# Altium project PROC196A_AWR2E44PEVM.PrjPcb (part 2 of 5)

## Sheet PROC196A_PMIC_Reference.SchDoc
size 431 x 279 mm; Date: Not shown in title block; ApprovedBy: Not shown in title block; CheckedBy: Not shown in title block; Author: Not shown in title block; CompanyName: Not shown in title block; Engineer: Not shown in title block; Organization: Not shown in title block; Address1: Not shown in title block; Address2: Not shown in title block; Address3: Not shown in title block; Address4: Not shown in title block; DocumentNumber: 6; Revision: Use project parameter SCH_Rev; SheetNumber: 6; SheetTotal: 25; PageSetup: Record=PageOptions¦CenterHorizontal=True¦CenterVertical=True¦PrintScale=1.00¦XCorrection=1.00¦YCorrection=1.00¦PrintKind=0¦BorderSize=5000000¦LeftOffset=0¦BottomOffset=0¦Orientation=2¦PaperLength=1000¦PaperWidth=1000¦Scale=100¦PaperSource=15¦PrintQuality=600¦MediaType=1¦DitherType=10¦PaperKind=Letter¦PrintScaleMode=1
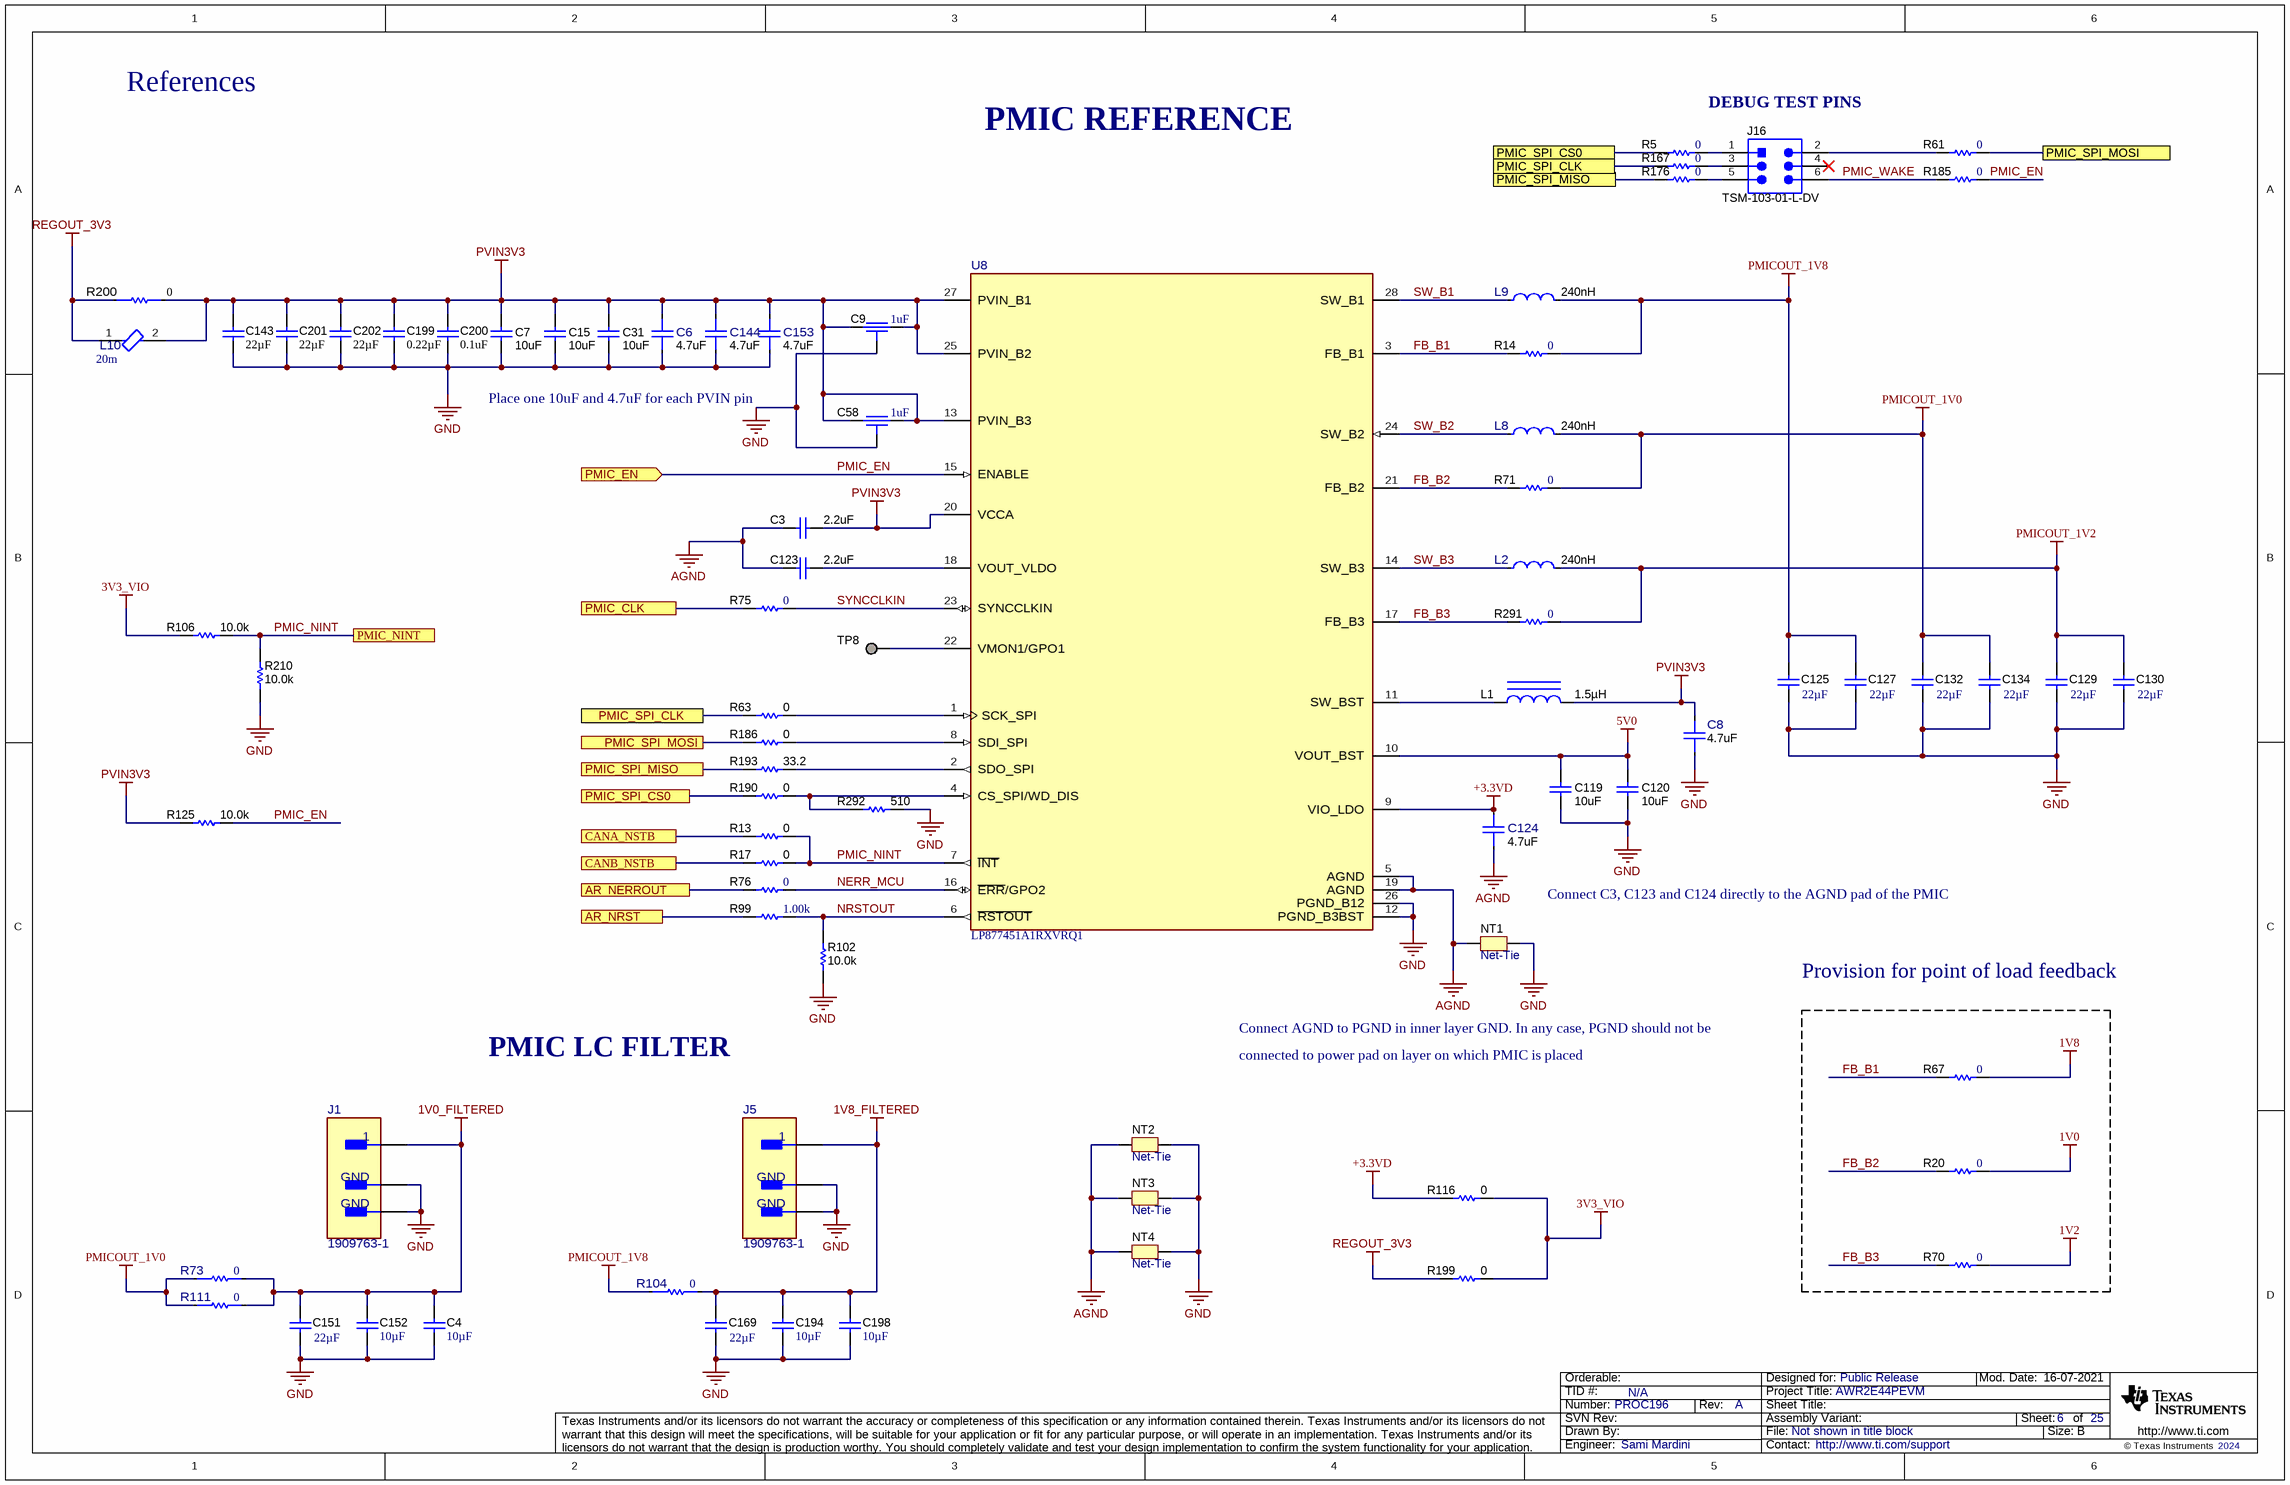
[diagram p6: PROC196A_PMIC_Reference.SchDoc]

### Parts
C3  ValueDisplayed: 2.2uF  [0603L]  (hidden comment: GCM188R70J225KE22D)
C4  Cap_F: 10µF  [0805L]  (hidden comment: C0805C106J8RACAUTO)
C6  ValueDisplayed: 4.7uF  [FP-GCJ188C70J475KE02J_0603-MFG]  (hidden comment: GCJ188C70J475KE02J)
C7  ValueDisplayed: 10uF  [0805L]  (hidden comment: GCM21BR71A106KE22L)
C8  ValueDisplayed: 4.7uF  [FP-GCJ188C70J475KE02J_0603-MFG]  (hidden comment: GCJ188C70J475KE02J)
C9  ValueDisplayed: 1uF  [FP-NFM18HC105C1C3D_0603-MFG]  (hidden comment: NFM18HC105C1C3D)
C15  ValueDisplayed: 10uF  [0805L]  (hidden comment: GCM21BR71A106KE22L)
C31  ValueDisplayed: 10uF  [0805L]  (hidden comment: GCM21BR71A106KE22L)
C58  ValueDisplayed: 1uF  [FP-NFM18HC105C1C3D_0603-MFG]  (hidden comment: NFM18HC105C1C3D)
C119  ValueDisplayed: 10uF  [0805L]  (hidden comment: GCM21BR71A106KE22L)
C120  ValueDisplayed: 10uF  [0805L]  (hidden comment: GCM21BR71A106KE22L)
C123  ValueDisplayed: 2.2uF  [0603L]  (hidden comment: GCM188R70J225KE22D)
C124  ValueDisplayed: 4.7uF  [FP-GCJ188C70J475KE02J_0603-MFG]  (hidden comment: GCJ188C70J475KE02J)
C125  ValueDisplayed: 22µF  [0805_155]  (hidden comment: CGA4J1X7T0J226M)
C127  ValueDisplayed: 22µF  [0805_155]  (hidden comment: CGA4J1X7T0J226M)
C129  ValueDisplayed: 22µF  [0805_155]  (hidden comment: CGA4J1X7T0J226M)
C130  ValueDisplayed: 22µF  [0805_155]  (hidden comment: CGA4J1X7T0J226M)
C132  ValueDisplayed: 22µF  [0805_155]  (hidden comment: CGA4J1X7T0J226M)
C134  ValueDisplayed: 22µF  [0805_155]  (hidden comment: CGA4J1X7T0J226M)
C143  ValueDisplayed: 22µF  [0805_155]  (hidden comment: CGA4J1X7T0J226M)
C144  ValueDisplayed: 4.7uF  [FP-GCJ188C70J475KE02J_0603-MFG]  (hidden comment: GCJ188C70J475KE02J)
C151  ValueDisplayed: 22µF  [0805_155]  (hidden comment: CGA4J1X7T0J226M)
C152  Cap_F: 10µF  [0805L]  (hidden comment: C0805C106J8RACAUTO)
C153  ValueDisplayed: 4.7uF  [FP-GCJ188C70J475KE02J_0603-MFG]  (hidden comment: GCJ188C70J475KE02J)
C169  ValueDisplayed: 22µF  [0805_155]  (hidden comment: CGA4J1X7T0J226M)
C194  Cap_F: 10µF  [0805L]  (hidden comment: C0805C106J8RACAUTO)
C198  Cap_F: 10µF  [0805L]  (hidden comment: C0805C106J8RACAUTO)
C199  ValueDisplayed: 0.22µF  [0402L]  (hidden comment: GCM155R71C224KE02D)
C200  ValueDisplayed: 0.1uF  [0402L]  (hidden comment: GCM155R71C104KA55D)
C201  ValueDisplayed: 22µF  [0805_155]  (hidden comment: CGA4J1X7T0J226M)
C202  ValueDisplayed: 22µF  [0805_155]  (hidden comment: CGA4J1X7T0J226M)
J1  1909763-1  [FP-1909763-1_SMT_JACK _CONN-MFG]
J5  1909763-1  [FP-1909763-1_SMT_JACK _CONN-MFG]
J16  TSM-103-01-L-DV  [Samtec_TSM-103-01-x-DV]
L1  ValueDisplayed: 1.5µH  [TFM201610ALMA]  (hidden comment: TFM201610ALMA1R5MTAA)
L2  Ind_H: 240nH  [FP-TFM201610ALMAR24MTAA_0806 (2016 Metric)-MFG]  (hidden comment: TFM201610ALMAR24MTAA)
L8  Ind_H: 240nH  [FP-TFM201610ALMAR24MTAA_0806 (2016 Metric)-MFG]  (hidden comment: TFM201610ALMAR24MTAA)
L9  Ind_H: 240nH  [FP-TFM201610ALMAR24MTAA_0806 (2016 Metric)-MFG]  (hidden comment: TFM201610ALMAR24MTAA)
L10  DCR_ohm: 20m  [FP-MPZ2012S101ATD25_0805-MFG]  (hidden comment: MPZ2012S101ATD25)
NT1  Net-Tie  [Net-Tie_50milWide_30milLong]  (net tie, no BOM)
NT2  Net-Tie  [Net-Tie_50milWide_30milLong]  (net tie, no BOM)
NT3  Net-Tie  [Net-Tie_50milWide_30milLong]  (net tie, no BOM)
NT4  Net-Tie  [Net-Tie_50milWide_30milLong]  (net tie, no BOM)
R5  ValueDisplayed: 0  [0402L]  (hidden comment: ERJ-2GE0R00X)
R13  ValueDisplayed: 0  [0402L]  (hidden comment: ERJ-2GE0R00X)
R14  ValueDisplayed: 0  [0402L]  (hidden comment: ERJ-2GE0R00X)
R17  ValueDisplayed: 0  [0402L]  (hidden comment: ERJ-2GE0R00X)
R20  ValueDisplayed: 0  [0402L]  (hidden comment: ERJ-2GE0R00X)
R61  ValueDisplayed: 0  [0402L]  (hidden comment: ERJ-2GE0R00X)
R63  ValueDisplayed: 0  [0402L]  (hidden comment: ERJ-2GE0R00X)
R67  ValueDisplayed: 0  [0402L]  (hidden comment: ERJ-2GE0R00X)
R70  ValueDisplayed: 0  [0402L]  (hidden comment: ERJ-2GE0R00X)
R71  ValueDisplayed: 0  [0402L]  (hidden comment: ERJ-2GE0R00X)
R73  value 0  [FP-HCJ0603ZT0R00_0603-MFG]  (hidden comment: HCJ0603ZT0R00)
R75  ValueDisplayed: 0  [0402L]  (hidden comment: ERJ-2GE0R00X)
R76  ValueDisplayed: 0  [0402L]  (hidden comment: ERJ-2GE0R00X)
R99  ValueDisplayed: 1.00k  [0402L]  (hidden comment: CRCW04021K00FKED)
R102  ValueDisplayed: 10.0k  [0402L]  (hidden comment: CRCW040210K0FKED)
R104  value 0  [FP-HCJ0603ZT0R00_0603-MFG]  (hidden comment: HCJ0603ZT0R00)
R106  ValueDisplayed: 10.0k  [0402L]  (hidden comment: CRCW040210K0FKED)
R111  value 0  [FP-HCJ0603ZT0R00_0603-MFG]  (hidden comment: HCJ0603ZT0R00)
R116  ValueDisplayed: 0  [0402L]  (hidden comment: CRCW04020000Z0EDHP)
R125  ValueDisplayed: 10.0k  [0402L]  (hidden comment: CRCW040210K0FKED)
R167  ValueDisplayed: 0  [0402L]  (hidden comment: ERJ-2GE0R00X)
R176  ValueDisplayed: 0  [0402L]  (hidden comment: ERJ-2GE0R00X)
R185  ValueDisplayed: 0  [0402L]  (hidden comment: ERJ-2GE0R00X)
R186  ValueDisplayed: 0  [0402L]  (hidden comment: ERJ-2GE0R00X)
R190  ValueDisplayed: 0  [0402L]  (hidden comment: ERJ-2GE0R00X)
R193  ValueDisplayed: 33.2  [0402L]  (hidden comment: CRCW040233R2FKED)
R199  ValueDisplayed: 0  [0402L]  (hidden comment: CRCW04020000Z0EDHP)
R200  Res_ohm: 0  [FP-HCJ0603ZT0R00_0603-MFG]  (hidden comment: HCJ0603ZT0R00)
R210  ValueDisplayed: 10.0k  [0402L]  (hidden comment: CRCW040210K0FKED)
R291  ValueDisplayed: 0  [0402L]  (hidden comment: ERJ-2GE0R00X)
R292  ValueDisplayed: 510  [0402L]  (hidden comment: ERJ-2GEJ511X)
TP8  TESTPOINT  [TP_25MIL-SMT]  (value not drawn)  (no BOM)
U8  LP877451A1RXVRQ1  [RXV0028A-MFG]

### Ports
AR_NERROUT, AR_NRST, CANA_NSTB, CANB_NSTB, PMIC_CLK, PMIC_EN (in), PMIC_NINT, PMIC_SPI_CLK, PMIC_SPI_CS0, PMIC_SPI_MISO, PMIC_SPI_MOSI

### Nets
1V0: R20.2
1V0_FILTERED: C4.1 C151.1 C152.1 J1.1 R73.2 R111.2
1V2: R70.2
1V8: R67.2
1V8_FILTERED: C169.1 C194.1 C198.1 J5.1 R104.2
3V3_VIO: R106.2 R116.2 R199.2
5V0: C119.1 C120.1 U8.10(VOUT_BST)
+3.3VD: C124.2 R116.1 U8.9(VIO_LDO)
AGND: C3.1 C123.1 C124.1 NT1.2 NT2.1 NT3.1 NT4.1 U8.5(AGND) U8.19(AGND)
GND: C4.2 C6.1 C7.2 C8.1 C9.2 C15.2 C31.2 C58.2 C119.2 C120.2 C125.2 C127.2 C129.2 C130.2 C132.2 C134.2 C143.2 C144.1 C151.2 C152.2 C153.1 C169.2 C194.2 C198.2 C199.2 C200.2 C201.2 C202.2 J1.2(GND) J1.3(GND) J5.2(GND) J5.3(GND) NT1.1 NT2.2 NT3.2 NT4.2 R102.2 R210.2 R292.1 U8.12(PGND_B3BST) U8.26(PGND_B12)
PMICOUT_1V0: C132.1 C134.1 L8.2 R71.2 R73.1 R111.1
PMICOUT_1V2: C129.1 C130.1 L2.2 R291.2
PMICOUT_1V8: C125.1 C127.1 L9.2 R14.2 R104.1
PVIN3V3: C3.2 C6.2 C7.1 C8.2 C9.1 C9.3 C15.1 C31.1 C58.1 C58.3 C143.1 C144.2 C153.2 C199.1 C200.1 C201.1 C202.1 L1.2 L10.2 R125.2 R200.2 U8.13(PVIN_B3) U8.20(VCCA) U8.25(PVIN_B2) U8.27(PVIN_B1)
REGOUT_3V3: L10.1 R199.1 R200.1
AR_NERROUT: R76.1 ; port AR_NERROUT
AR_NRST: R99.1 ; port AR_NRST
CANA_NSTB: R13.1 ; port CANA_NSTB
CANB_NSTB: R17.1 ; port CANB_NSTB
FB_B1: R14.1 R67.1 U8.3(FB_B1)
FB_B2: R20.1 R71.1 U8.21(FB_B2)
FB_B3: R70.1 R291.1 U8.17(FB_B3)
NERR_MCU: R76.2 U8.16(~{ERR}/GPO2)
NRSTOUT: R99.2 R102.1 U8.6(~{RSTOUT})
PMIC_CLK: R75.1 ; port PMIC_CLK
PMIC_EN: R125.1 R185.2 U8.15(ENABLE) ; port PMIC_EN
PMIC_NINT: R13.2 R17.2 R106.1 R210.1 U8.7(~{INT}) ; port PMIC_NINT
PMIC_SPI_CLK: R63.2 R167.1 ; port PMIC_SPI_CLK
PMIC_SPI_CS0: R5.1 R190.1 ; port PMIC_SPI_CS0
PMIC_SPI_MISO: R176.1 R193.2 ; port PMIC_SPI_MISO
PMIC_SPI_MOSI: R61.2 R186.2 ; port PMIC_SPI_MOSI
PMIC_WAKE: J16.6 R185.1
SW_B1: L9.1 U8.28(SW_B1)
SW_B2: L8.1 U8.24(SW_B2)
SW_B3: L2.1 U8.14(SW_B3)
SYNCCLKIN: R75.2 U8.23(SYNCCLKIN)
NetC123_2: C123.2 U8.18(VOUT_VLDO)
NetJ16_1: J16.1 R5.2
NetJ16_2: J16.2 R61.1
NetJ16_3: J16.3 R167.2
NetJ16_5: J16.5 R176.2
NetL1_1: L1.1 U8.11(SW_BST)
NetR63_1: R63.1 U8.1(SCK_SPI)
NetR186_1: R186.1 U8.8(SDI_SPI)
NetR190_2: R190.2 R292.2 U8.4(CS_SPI/WD_DIS)
NetR193_1: R193.1 U8.2(SDO_SPI)
NetTP8_1: TP8.1 U8.22(VMON1/GPO1)

Not connected (* = marked no-connect by the designer): J16 4*

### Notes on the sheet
- References
- PMIC REFERENCE
- DEBUG TEST PINS
- Place one 10uF and 4.7uF for each PVIN pin
- Connect C3, C123 and C124 directly to the AGND pad of the PMIC
- Connect AGND to PGND in inner layer GND. In any case, PGND should not be
- Provision for point of load feedback
- PMIC LC FILTER
- connected to power pad on layer on which PMIC is placed

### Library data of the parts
C3 C123 = CMP-0007134-5: CAP, CERM, 2.2 uF, 6.3 V, +/- 10%, X7R, AEC-Q200 Grade 1, 0603; Manufacturer: MuRata; TaMin_C: -55°C; Polarized: N; SizeAreaWB_mm2: 4.68; Value1: Unknown; U/M: EA; Value: 2.2uF; TaMax_C: 125°C; SizeZ_mm: 1; SizeX_mm: 1.6; SizeY_mm: 0.8; Cap_Case: 0603; Value2: 6.3V; SizeArea_mm2: 1.28; AEC Qualified: Y; Cap_F: 2.2µF; AEC Category: Q200
C4 C152 C194 C198 = CMP-0081061-1: CAP, CERM, 10 µF, 10 V,+/- 5%, X7R, AEC-Q200 Grade 1, 0805; Manufacturer: Kemet; TaMin_C: -55°C; Polarized: N; SizeAreaWB_mm2: 6.75; U/M: EA; Value: 10uF; TaMax_C: 125°C; SizeZ_mm: 1.45; SizeX_mm: 2; SizeY_mm: 1.25; Cap_Case: 0805; Value2: 10V; SizeArea_mm2: 2.5; AEC Qualified: Y; AEC Grade: 1; AEC Category: Q200
C6 C8 C124 C144 C153 = CMP-0091520-1: Cap Ceramic Multilayer 4.7uF 6.3V DC 10% SMD Paper T/R; Manufacturer: Murata; AEC Grade: Grade 1; TempCo: 22%; SizeZ_mm: 1mm; Temperature Characteristic: X7S; Cap_F: 4.7µF; Value: 4.7µF; AEC Qualified: Yes
C7 C15 C31 C119 C120 = CMP-0008017-2: CAP, CERM, 10 uF, 10 V, +/- 10%, X7R, 0805; Manufacturer: MuRata; TaMin_C: -55°C; Polarized: N; SizeAreaWB_mm2: 6.75; Value1: Unknown; U/M: EA; Value: 10uF; TaMax_C: 125°C; SizeZ_mm: 1.45; SizeX_mm: 2; SizeY_mm: 1.25; Cap_Case: 0805; Value2: 10V; SizeArea_mm2: 2.5; Cap_F: 10µF; AEC Category: Q200
C9 C58 = CMP-0088247-2: 3 Terminals Low ESL Chip Multilayer Ceramic Capacitors for Automotive; Manufacturer: Murata; VDC_V: 16V; SizeZ_mm: 0.7mm; Tolerance_%: 20%; AEC Grade: Grade 1; Cap_F: 1µF; AEC Qualified: Yes
C125 C127 C129 C130 C132 C134 = CMP-0860846-1: CAP, CERM, 22 µF, 6.3 V,+/- 20%, X7T, AEC-Q200 Grade 1, 0805; Manufacturer: TDK; Alternate PartNumber: CGA4J1X7T0J226M125AC; TaMin_C: -55°C; Polarized: N; SizeAreaWB_mm2: 6.75; U/M: EA; Value: 22uF; TaMax_C: 125°C; SizeZ_mm: 1.55; SizeX_mm: 2; SizeY_mm: 1.25; Cap_Case: 0805; Value2: 6.3V; SizeArea_mm2: 2.5; AEC Qualified: Y; AEC Grade: 1; AEC Category: Q200
C143 C201 C202 = CMP-0860846-1: CAP, CERM, 22 µF, 6.3 V,+/- 20%, X7T, AEC-Q200 Grade 1, 0805; Manufacturer: TDK; AEC Grade: 1; Value2: 6.3V; U/M: EA; Value: 22uF; TaMin_C: -55°C; TaMax_C: 125°C; SizeArea_mm2: 2.5; SizeAreaWB_mm2: 6.75; SizeX_mm: 2; Polarized: N; Cap_Case: 0805; AEC Qualified: Y; AEC Category: Q200; SizeZ_mm: 1.55; SizeY_mm: 1.25
C151 C169 = CMP-0860846-1: CAP, CERM, 22 µF, 6.3 V,+/- 20%, X7T, AEC-Q200 Grade 1, 0805; Manufacturer: TDK; TaMin_C: -55°C; Polarized: N; SizeAreaWB_mm2: 6.75; U/M: EA; Value: 22uF; TaMax_C: 125°C; SizeZ_mm: 1.55; SizeX_mm: 2; SizeY_mm: 1.25; Cap_Case: 0805; Value2: 6.3V; SizeArea_mm2: 2.5; AEC Qualified: Y; AEC Grade: 1; AEC Category: Q200
C199 = CMP-0078265-1: CAP, CERM, 0.22 µF, 16 V,+/- 10%, X7R, AEC-Q200 Grade 1, 0402; Manufacturer: MuRata; TaMin_C: -55°C; Polarized: N; SizeAreaWB_mm2: 3; U/M: EA; Value: 0.22uF; TaMax_C: 125°C; SizeZ_mm: 0.6; SizeX_mm: 1; SizeY_mm: 0.5; Cap_Case: 0402; Value2: 16V; AEC Qualified: Y; Cap_F: 220nF; AEC Category: Q200
C200 = CMP-0006351-2: CAP, CERM, 0.1 uF, 16 V, +/- 10%, X7R, 0402; Manufacturer: MuRata; TaMin_C: -55°C; Polarized: N; SizeAreaWB_mm2: 3; Value1: Unknown; U/M: EA; Value: 0.1uF; TaMax_C: 125°C; SizeZ_mm: 0.6; SizeX_mm: 1; SizeY_mm: 0.5; Cap_Case: 0402; Value2: 16V; Cap_F: 100nF; AEC Category: Q200
J1 J5 = CMP-0091846-1: U.FL (UMCC) Connector Jack, Male Pin 50Ohm Surface Mount Solder; Manufacturer: TE Connectivity; Conn Orientation: Vertical; AEC Qualified: No; SizeZ_mm: 1.5mm; Impedance: 50Ω; Frequency_Fixed: 0-6GHz; ContactFinish: Gold,Nickel; Dielectric Material: Liquid Crystal Polymer
J16 = CMP-0075648-2: Header, 2.54mm, 3x2, Gold, SMT; Manufacturer: Samtec; Pitch_mm: 2.54; Gender: Male; Cert_CSA: Y; Green_REACh: Passed; Current_A: 4.9A; Voltage_V: 475V; Shrouded: N; Green_Lifecycle: Active; Row_Count: 2
L1 = CMP-0081093-1: Inductor, Shielded, Metal Composite, 1.5 µH, 2.3 A, 0.11 ohm, AEC-Q200 Grade 0, SMD; Manufacturer: TDK; Isat: 2.8A @ 30% inductance drop; Irms: 2.3A @ 40C rise; SizeAreaWB_mm2: 7.8; DCR_ohm: 0.11; Value: 1.5uH; Imax_A: 2.3A; SizeZ_mm: 1; SizeX_mm: 2; SizeY_mm: 1.6; SizeArea_mm2: 3.2; AEC Qualified: Y; AEC Grade: 0; AEC Category: Q200
L2 L8 L9 = CMP-0091696-1: 240nH Shielded Thin Film Inductor 5A 23mOhm Max 0806 (2016 Metric); Manufacturer: TDK; SizeZ_mm: 1mm; Material: Metal; Irms: 6.5A; Shrouded: true; Value: 0.24uH; AEC Qualified: Yes; DCR_ohm: 0.023; AEC Grade: Grade 0; Test Frequency: 1MHz; Tolerance_%: 20%
L10 = CMP-0089947-1: 100 Ohms @ 100MHz 1 Power Line Ferrite Bead 0805 (2012 Metric) 4A 20mOhm; Manufacturer: TDK; AEC Grade: Grade 1; Impedance At Frequency: 100Ω @ 100MHz; SizeZ_mm: 1.05mm; AEC Qualified: Yes; Tolerance_%: 25%
NT1 = CMP-0078142-4: Single point connection between nets.
NT2-NT4 = CMP-0078142-3: Single point connection between nets.
R5 R14 R20 R61 R67 R70 R71 R75 R76 R167 R176 R185 R291 = CMP-0026992-3: RES, 0, 5%, 0.1 W, AEC-Q200 Grade 0, 0402; Manufacturer: Panasonic; Power_W: 100mW; TempCo: 600 ppm/C; Value_Code: 0000; Value: 0; EIA_Code: E24; SizeX_mm: 1; SizeY_mm: 0.5; SizeZ_mm: 0.6; Value2: 0.1W; CompType: Resistor; AEC Qualified: Y; VDC_V: 50V; AEC Category: Q200; SizeAreaWB_mm2: 3; INSTALLATION: DNP
R13 R17 R63 R186 R190 = CMP-0026992-3: RES, 0, 5%, 0.1 W, AEC-Q200 Grade 0, 0402; Manufacturer: Panasonic; Power_W: 100mW; TempCo: 600 ppm/C; Value_Code: 0000; Value: 0; EIA_Code: E24; SizeX_mm: 1; SizeY_mm: 0.5; SizeZ_mm: 0.6; Value2: 0.1W; AEC Qualified: Y; VDC_V: 50V; AEC Category: Q200; SizeAreaWB_mm2: 3
R73 R104 R111 = CMP-0091690-1: RES 0 OHM JUMPER 1/4W 0603; Manufacturer: Stackpole Electronics; Power_W: 250mW; AEC Grade: Grade 0; AEC Qualified: Yes; SizeZ_mm: 0.7mm
R99 = CMP-0026071-3: RES, 1.00 k, 1%, 0.063 W, AEC-Q200 Grade 0, 0402; Manufacturer: Vishay-Dale; Power_W: 63mW; TempCo: 100 ppm/C; Value_Code: 1k00; Value: 1.00k; EIA_Code: E96; Res_ohm: 1k; SizeX_mm: 1; SizeY_mm: 0.5; SizeZ_mm: 0.6; Value2: 0.063W; AEC Qualified: Y; VDC_V: 50V; AEC Category: Q200; AEC Grade: 0
R102 R106 R125 R210 = CMP-0025958-3: RES, 10.0 k, 1%, 0.063 W, AEC-Q200 Grade 0, 0402; Manufacturer: Vishay-Dale; Power_W: 63mW; TempCo: 100 ppm/C; Value_Code: 10k0; Value: 10.0k; EIA_Code: E96; Res_ohm: 10k; SizeX_mm: 1; SizeY_mm: 0.5; SizeZ_mm: 0.6; Value2: 0.063W; AEC Qualified: Y; VDC_V: 50V; AEC Category: Q200; AEC Grade: 0
R116 R199 = CMP-0081856-1: RES, 0, 0%, 0.2 W, AEC-Q200 Grade 0, 0402; Manufacturer: Vishay-Dale; SizeAreaWB_mm2: 3; SizeArea_mm2: 0.5; AEC Qualified: Y; AEC Category: Q200; Value: 0; SizeZ_mm: 0.6; Power_W: 200mW; VDC_V: 50V; Value2: 0.2W; SizeX_mm: 1
R193 = CMP-0026299-2: RES, 33.2, 1%, 0.063 W, AEC-Q200 Grade 0, 0402; Manufacturer: Vishay-Dale; Power_W: 63mW; TempCo: 100 ppm/C; Value_Code: 33R2; Value: 33.2; EIA_Code: E96; SizeX_mm: 1; SizeY_mm: 0.5; SizeZ_mm: 0.6; Value2: 0.063W; AEC Qualified: Y; VDC_V: 50V; AEC Category: Q200; AEC Grade: 0
R200 = CMP-0091690-1: RES 0 OHM JUMPER 1/4W 0603; Manufacturer: Stackpole Electronics; Power_W: 250mW; AEC Grade: Grade 0; AEC Qualified: Yes; SizeZ_mm: 0.7mm; Value: 0
R292 = CMP-0078212-1: RES, 510, 5%, 0.1 W, AEC-Q200 Grade 0, 0402; Manufacturer: Panasonic; Value_Code: 510R; SizeArea_mm2: 0.5; AEC Qualified: Y; AEC Category: Q200; Value: 510; SizeZ_mm: 0.6; EIA_Code: E24; TempCo: 200 ppm/C; AEC Grade: 0; Power_W: 100mW; VDC_V: 50V; Value2: 0.1W; U/M: EA; SizeX_mm: 1
TP8 = CMP-0078143-3: TEST POINT.  No entry in BOM.
U8 = CMP-0091078-3: Three Buck Converters and 5-V Boost for AWR and IWR Radar Sensors; Manufacturer: Texas Instruments; CompType: IC; AEC Category: Q200; Standoff Height: 0mm; Min Supply Voltage: 3V; TJmax_C: +150°C; Switching Frequency: 4.4-8.8-17.6MHz; Nominal Supply Current: 3uA; TaMax_C: +125°C; Max Supply Voltage: 4V; TaMin_C: -40°C; Number Of Outputs: 4; SizeZ_mm: 1mm; Output Voltage: 0.9-1.9V; AEC Qualified: Yes; AEC Grade: Grade 1; Output Type: AdjustableProgrammable

## Sheet PROC196A_3V3_Supply_Reference.SchDoc
size 431 x 279 mm; Date: Not shown in title block; ApprovedBy: Not shown in title block; CheckedBy: Not shown in title block; Author: Not shown in title block; CompanyName: Not shown in title block; Engineer: Not shown in title block; Organization: Not shown in title block; Address1: Not shown in title block; Address2: Not shown in title block; Address3: Not shown in title block; Address4: Not shown in title block; DocumentNumber: 7; Revision: Use project parameter SCH_Rev; SheetNumber: 7; SheetTotal: 25; PageSetup: Record=PageOptions¦CenterHorizontal=True¦CenterVertical=True¦PrintScale=1.00¦XCorrection=1.00¦YCorrection=1.00¦PrintKind=0¦BorderSize=5000000¦LeftOffset=0¦BottomOffset=0¦Orientation=2¦PaperLength=1000¦PaperWidth=1000¦Scale=100¦PaperSource=15¦PrintQuality=600¦MediaType=1¦DitherType=10¦PaperKind=Letter¦PrintScaleMode=1
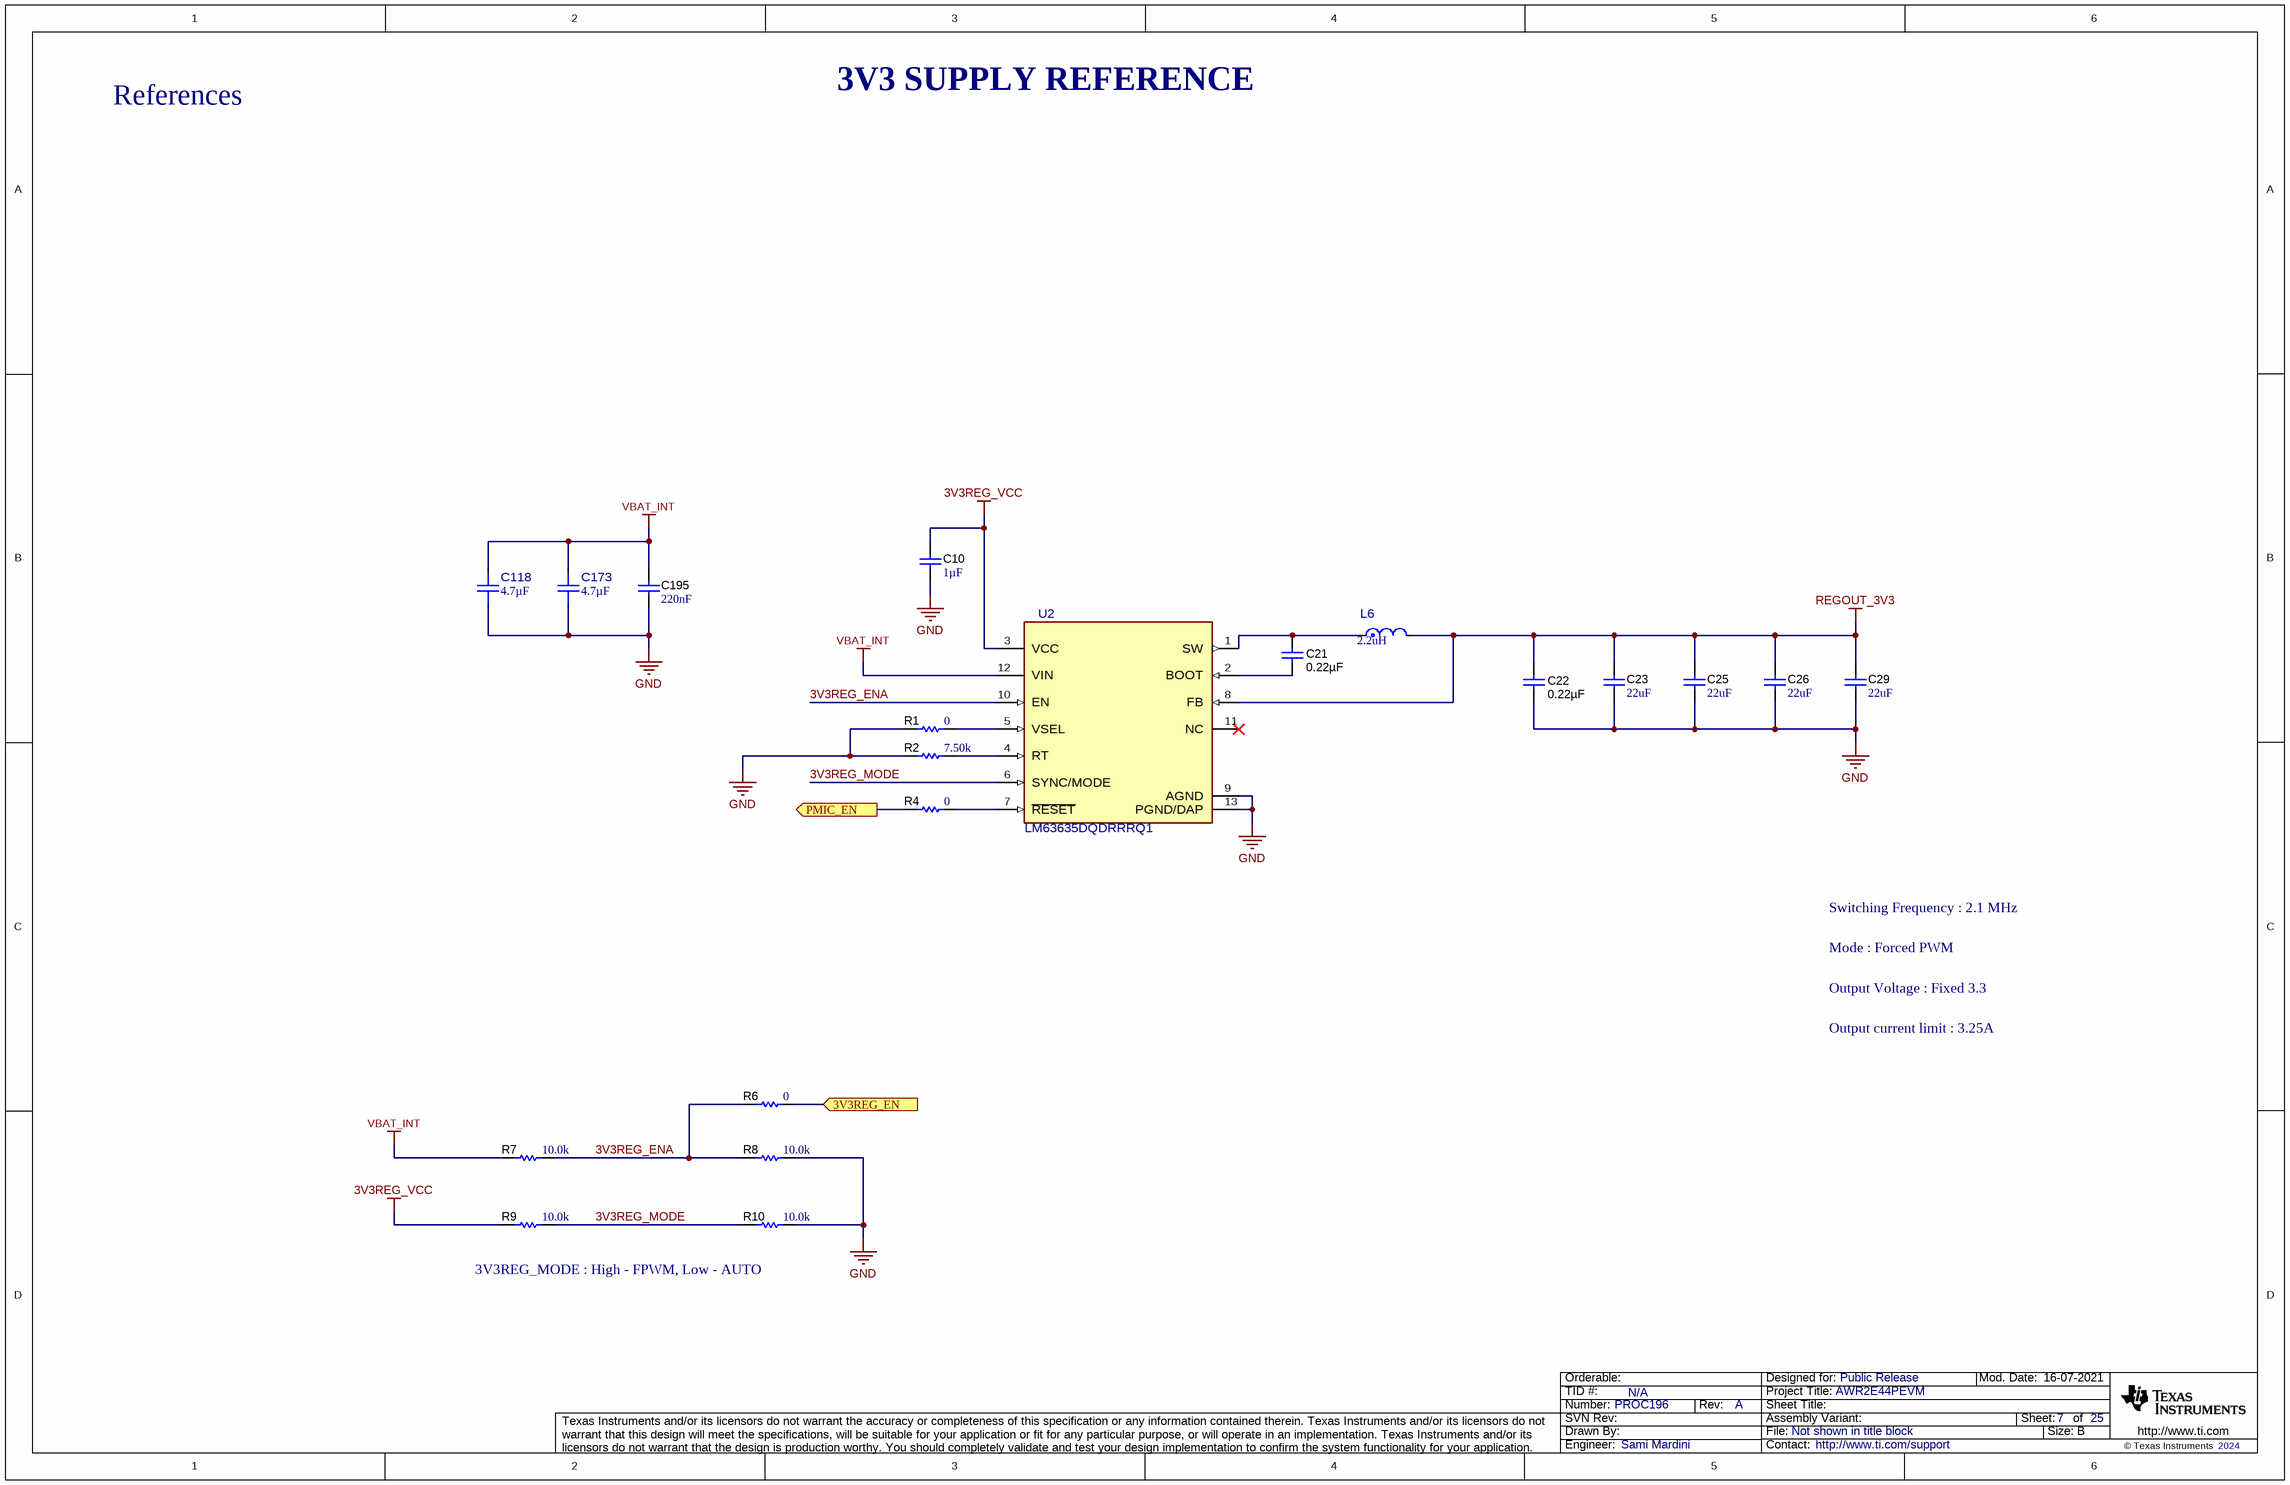
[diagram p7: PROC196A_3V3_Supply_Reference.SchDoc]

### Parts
C10  Cap_F: 1µF  [0603L]  (hidden comment: GCM188R71C105KA64D)
C21  ValueDisplayed: 0.22µF  [0402L]  (hidden comment: GCM155R71C224KE02D)
C22  ValueDisplayed: 0.22µF  [0402L]  (hidden comment: GCM155R71C224KE02D)
C23  ValueDisplayed: 22uF  [1206_180L]  (hidden comment: GCM31CR71A226KE02L)
C25  ValueDisplayed: 22uF  [1206_180L]  (hidden comment: GCM31CR71A226KE02L)
C26  ValueDisplayed: 22uF  [1206_180L]  (hidden comment: GCM31CR71A226KE02L)
C29  ValueDisplayed: 22uF  [1206_180L]  (hidden comment: GCM31CR71A226KE02L)
C118  Cap_F: 4.7µF  [FP-CGA4J1X7R1H475K125AC_0805-MFG]  (hidden comment: CGA4J1X7R1H475K125AC)
C173  Cap_F: 4.7µF  [FP-CGA4J1X7R1H475K125AC_0805-MFG]  (hidden comment: CGA4J1X7R1H475K125AC)
C195  Cap_F: 220nF  [0603L]  (hidden comment: CGA3E3X7R1H224K080AB)
L6  value 2.2uH  [FP-XEL4030-222MEC_SMT2_4MM0_4MM0-MFG]  (hidden comment: XEL4030-222MEC)
R1  ValueDisplayed: 0  [0402L]  (hidden comment: ERJ-2GE0R00X)
R2  ValueDisplayed: 7.50k  [0402L]  (hidden comment: CRCW04027K50FKED)
R4  ValueDisplayed: 0  [0402L]  (hidden comment: ERJ-2GE0R00X)
R6  ValueDisplayed: 0  [0402L]  (hidden comment: ERJ-2GE0R00X)
R7  ValueDisplayed: 10.0k  [0402L]  (hidden comment: CRCW040210K0FKED)
R8  ValueDisplayed: 10.0k  [0402L]  (hidden comment: CRCW040210K0FKED)
R9  ValueDisplayed: 10.0k  [0402L]  (hidden comment: CRCW040210K0FKED)
R10  ValueDisplayed: 10.0k  [0402L]  (hidden comment: CRCW040210K0FKED)
U2  LM63635DQDRRRQ1  [DRR0012E-MFG]

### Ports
3V3REG_EN (in), PMIC_EN (out)

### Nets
3V3REG_VCC: C10.1 R9.2 U2.3(VCC)
GND: C10.2 C22.1 C23.2 C25.2 C26.2 C29.2 C118.1 C173.1 C195.2 R1.2 R2.1 R8.2 R10.1 U2.9(AGND) U2.13(PGND/DAP)
REGOUT_3V3: C22.2 C23.1 C25.1 C26.1 C29.1 L6.2 U2.8(FB)
VBAT_INT: C118.2 C173.2 C195.1 R7.1 U2.12(VIN)
3V3REG_EN: R6.2 ; port 3V3REG_EN
3V3REG_ENA: R6.1 R7.2 R8.1 U2.10(EN)
3V3REG_MODE: R9.1 R10.2 U2.6(SYNC/MODE)
PMIC_EN: R4.1 ; port PMIC_EN
NetC21_1: C21.1 U2.2(BOOT)
NetC21_2: C21.2 L6.1 U2.1(SW)
NetR1_1: R1.1 U2.5(VSEL)
NetR2_2: R2.2 U2.4(RT)
NetR4_2: R4.2 U2.7(~{RESET})

Not connected (* = marked no-connect by the designer): U2 11(NC)*

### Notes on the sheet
- 3V3 SUPPLY REFERENCE
- References
- Switching Frequency : 2.1 MHz
- Mode : Forced PWM
- Output Voltage : Fixed 3.3
- Output current limit : 3.25A
- 3V3REG_MODE : High - FPWM, Low - AUTO

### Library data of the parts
C10 = CMP-0007136-5: CAP, CERM, 1 uF, 16 V, +/- 10%, X7R, AEC-Q200 Grade 1, 0603; Manufacturer: MuRata; TaMin_C: -55°C; Polarized: N; SizeAreaWB_mm2: 4.68; Value1: Unknown; U/M: EA; Value: 1uF; TaMax_C: 125°C; SizeZ_mm: 1; SizeX_mm: 1.6; SizeY_mm: 0.8; Cap_Case: 0603; Value2: 16V; SizeArea_mm2: 1.28; AEC Qualified: Y; AEC Category: Q200
C21 C22 = CMP-0078265-1: CAP, CERM, 0.22 µF, 16 V,+/- 10%, X7R, AEC-Q200 Grade 1, 0402; Manufacturer: MuRata; TaMin_C: -55°C; Polarized: N; SizeAreaWB_mm2: 3; U/M: EA; Value: 0.22uF; TaMax_C: 125°C; SizeZ_mm: 0.6; SizeX_mm: 1; SizeY_mm: 0.5; Cap_Case: 0402; Value2: 16V; CompType: Capacitor; AEC Qualified: Y; Cap_F: 220nF; AEC Category: Q200
C23 C25 C26 C29 = CMP-0008811-3: CAP, CERM, 22 uF, 10 V, +/- 10%, X7R, AEC-Q200 Grade 1, 1206; Manufacturer: MuRata; SizeX_mm: 3.2; SizeArea_mm2: 5.12; Polarized: N; SizeY_mm: 1.6; Value2: 10V; TaMin_C: -55°C; SizeZ_mm: 1.8; Cap_Case: 1206; AEC Grade: 1; Value1: Unknown; U/M: EA; AEC Qualified: Y; SizeAreaWB_mm2: 10.92; AEC Category: Q200; Value: 22uF; Cap_F: 22µF; TaMax_C: 125°C
C118 C173 = CMP-0090082-1: Cap Ceramic 4.7uF 50V X7R 10% Pad SMD 0805 +125°C Automotive T/R; Manufacturer: TDK Corporation; SizeZ_mm: 1.45mm; Tolerance_%: 0.1%; AEC Qualified: Yes; TempCo: 15%; AEC Grade: Grade 1; Value: 4.7µF
C195 = CMP-0007094-5: CAP, CERM, 0.22 uF, 50 V, +/- 10%, X7R, AEC-Q200 Grade 1, 0603; Manufacturer: TDK; TaMin_C: -55°C; ESR_ohm: 0.021699; Polarized: N; SizeAreaWB_mm2: 4.68; Value1: 0.021699 ohm; U/M: EA; Value: 0.22uF; TaMax_C: 125°C; SizeZ_mm: 1; SizeX_mm: 1.6; SizeY_mm: 0.8; Cap_Case: 0603; Value2: 50V; SizeArea_mm2: 1.28; AEC Qualified: Y; IRMS_A: 1.12496A; AEC Category: Q200
L6 = CMP-0120010-1: Ultra-Low Loss Shielded Power Inductors 2.2µH ±20% 7.8A 22.1mOhms; Manufacturer: Coilcraft; AEC Grade: Grade 1; AEC Qualified: Yes; DCR_ohm: 22.1m; Isat: 6.1A; Material: Composite; SizeZ_mm: 3.1mm; Self Resonant Frequency: 40MHz; Shrouded: true; TaMax_C: +125°C; TaMin_C: -40°C; Test Frequency: 1MHz
R1 R4 R6 = CMP-0026992-3: as R5 on sheet PROC196A_PMIC_Reference
R2 = CMP-0026555-2: RES, 7.50 k, 1%, 0.063 W, AEC-Q200 Grade 0, 0402; Manufacturer: Vishay-Dale; Power_W: 63mW; TempCo: 100 ppm/C; Value_Code: 7k50; Value: 7.50k; EIA_Code: E96; Res_ohm: 7.5k; SizeX_mm: 1; SizeY_mm: 0.5; SizeZ_mm: 0.6; Value2: 0.063W; AEC Qualified: Y; VDC_V: 50V; AEC Category: Q200; AEC Grade: 0
R7-R10 = CMP-0025958-3: as R102 on sheet PROC196A_PMIC_Reference
U2 = CMP-0088353-1: 3.5-V to 36-V, 1.5-A, and 2.5-A Automotive Step-down Voltage Converter; Manufacturer: Texas Instruments; Max Supply Voltage: 32V; Number Of Outputs: 1; Standoff Height: 0mm; Output Type: Fixed,AdjustableProgrammable; Switching Topology: Buck; TaMax_C: +125°C; Min Supply Voltage: 3.5V; Max Duty Cycle: 98%; TaMin_C: -40°C; AEC Qualified: Yes; Output Voltage: 3.3/5/1-20V; AEC Grade: Grade 1; TJmax_C: +150°C; Nominal Supply Current: 23uA; SizeZ_mm: 0.8mm; Switching Frequency: 400/2100/250-2200kHz

## Sheet PROC196A_SOP_Reference.SchDoc
size 431 x 279 mm; Date: Not shown in title block; ApprovedBy: Not shown in title block; CheckedBy: Not shown in title block; Author: Not shown in title block; CompanyName: Not shown in title block; Engineer: Not shown in title block; Organization: Not shown in title block; Address1: Not shown in title block; Address2: Not shown in title block; Address3: Not shown in title block; Address4: Not shown in title block; DocumentNumber: 8; Revision: Use project parameter SCH_Rev; SheetNumber: 8; SheetTotal: 25; PageSetup: Record=PageOptions¦CenterHorizontal=True¦CenterVertical=True¦PrintScale=1.00¦XCorrection=1.00¦YCorrection=1.00¦PrintKind=0¦BorderSize=5000000¦LeftOffset=0¦BottomOffset=0¦Orientation=2¦PaperLength=1000¦PaperWidth=1000¦Scale=100¦PaperSource=15¦PrintQuality=600¦MediaType=1¦DitherType=10¦PaperKind=Letter¦PrintScaleMode=1
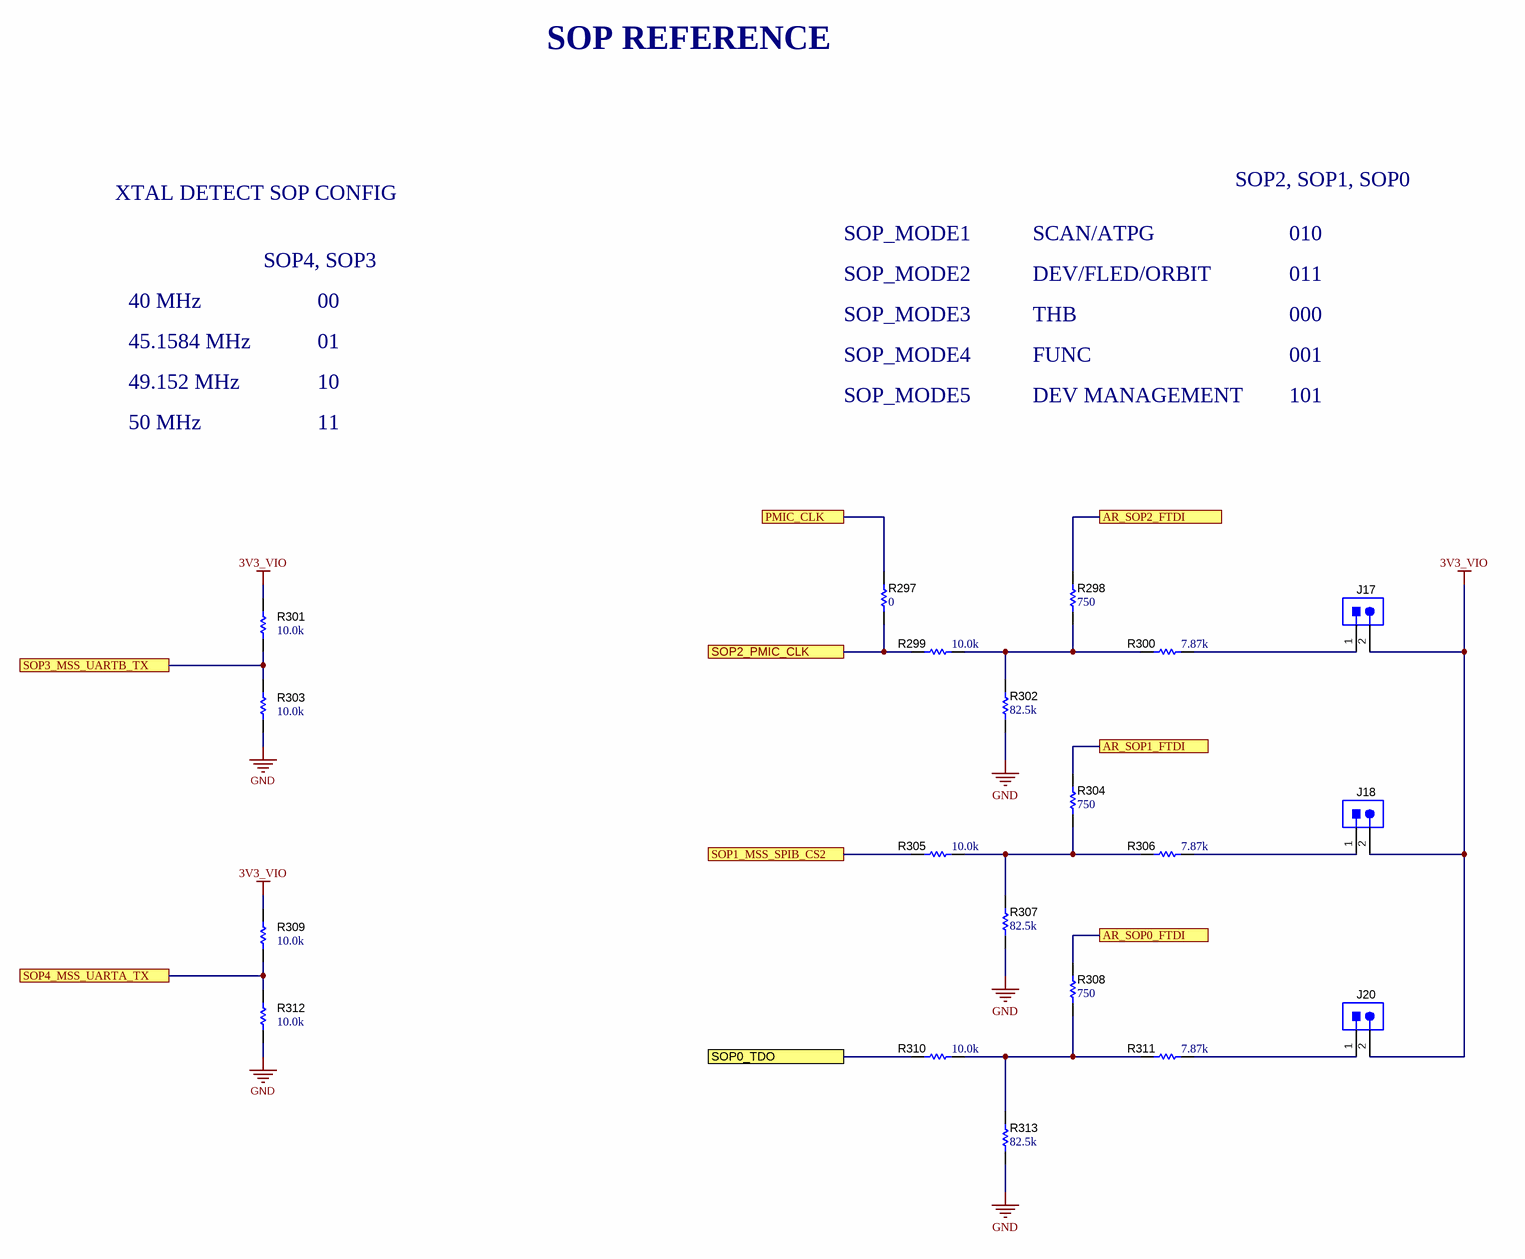
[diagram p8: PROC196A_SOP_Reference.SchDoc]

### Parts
J17  TSW-102-07-G-S  [TSW-102-07-G-S]  (value not drawn)
J18  TSW-102-07-G-S  [TSW-102-07-G-S]  (value not drawn)
J20  TSW-102-07-G-S  [TSW-102-07-G-S]  (value not drawn)
R297  ValueDisplayed: 0  [0402L]  (hidden comment: ERJ-2GE0R00X)
R298  ValueDisplayed: 750  [0402L]  (hidden comment: CRCW0402750RFKED)
R299  ValueDisplayed: 10.0k  [0402L]  (hidden comment: CRCW040210K0FKED)
R300  ValueDisplayed: 7.87k  [0402L]  (hidden comment: CRCW04027K87FKED)
R301  ValueDisplayed: 10.0k  [0402L]  (hidden comment: CRCW040210K0FKED)
R302  ValueDisplayed: 82.5k  [0402L]  (hidden comment: CRCW040282K5FKED)
R303  ValueDisplayed: 10.0k  [0402L]  (hidden comment: CRCW040210K0FKED)
R304  ValueDisplayed: 750  [0402L]  (hidden comment: CRCW0402750RFKED)
R305  ValueDisplayed: 10.0k  [0402L]  (hidden comment: CRCW040210K0FKED)
R306  ValueDisplayed: 7.87k  [0402L]  (hidden comment: CRCW04027K87FKED)
R307  ValueDisplayed: 82.5k  [0402L]  (hidden comment: CRCW040282K5FKED)
R308  ValueDisplayed: 750  [0402L]  (hidden comment: CRCW0402750RFKED)
R309  ValueDisplayed: 10.0k  [0402L]  (hidden comment: CRCW040210K0FKED)
R310  ValueDisplayed: 10.0k  [0402L]  (hidden comment: CRCW040210K0FKED)
R311  ValueDisplayed: 7.87k  [0402L]  (hidden comment: CRCW04027K87FKED)
R312  ValueDisplayed: 10.0k  [0402L]  (hidden comment: CRCW040210K0FKED)
R313  ValueDisplayed: 82.5k  [0402L]  (hidden comment: CRCW040282K5FKED)

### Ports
AR_SOP0_FTDI, AR_SOP1_FTDI, AR_SOP2_FTDI, PMIC_CLK, SOP0_TDO, SOP1_MSS_SPIB_CS2, SOP2_PMIC_CLK, SOP3_MSS_UARTB_TX, SOP4_MSS_UARTA_TX

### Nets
3V3_VIO: J17.2 J18.2 J20.2 R301.2 R309.2
GND: R302.1 R303.1 R307.1 R312.1 R313.1
AR_SOP0_FTDI: R308.2 ; port AR_SOP0_FTDI
AR_SOP1_FTDI: R304.2 ; port AR_SOP1_FTDI
AR_SOP2_FTDI: R298.2 ; port AR_SOP2_FTDI
PMIC_CLK: R297.2 ; port PMIC_CLK
SOP0_TDO: R310.1 ; port SOP0_TDO
SOP1_MSS_SPIB_CS2: R305.1 ; port SOP1_MSS_SPIB_CS2
SOP2_PMIC_CLK: R297.1 R299.1 ; port SOP2_PMIC_CLK
SOP3_MSS_UARTB_TX: R301.1 R303.2 ; port SOP3_MSS_UARTB_TX
SOP4_MSS_UARTA_TX: R309.1 R312.2 ; port SOP4_MSS_UARTA_TX
NetJ17_1: J17.1 R300.2
NetJ18_1: J18.1 R306.2
NetJ20_1: J20.1 R311.2
NetR298_1: R298.1 R299.2 R300.1 R302.2
NetR304_1: R304.1 R305.2 R306.1 R307.2
NetR308_1: R308.1 R310.2 R311.1 R313.2

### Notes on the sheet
- SOP REFERENCE
- XTAL DETECT SOP CONFIG
- SOP2, SOP1, SOP0
- SOP4, SOP3
- SOP_MODE1
- SCAN/ATPG
- 010
- 40 MHz
- 00
- SOP_MODE2
- SOP_MODE3
- DEV/FLED/ORBIT
- THB
- 011
- 000
- 45.1584 MHz
- 49.152 MHz
- 01
- 10
- SOP_MODE4
- SOP_MODE5
- FUNC
- DEV MANAGEMENT
- 001
- 101
- 50 MHz
- 11

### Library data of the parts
J17 J18 J20 = CMP-0075405-3: Header, 100mil, 2x1, Gold, TH; Manufacturer: Samtec; Current_A: 6.3A; Green_Lifecycle: Active; Pitch_mm: 2.54; Cert_CSA: Y; Cert_VDE: N; Green_REACh: Passed; Row_Count: 1; Gender: Male; Voltage_V: 550V
R297 = CMP-0026992-3: as R13 on sheet PROC196A_PMIC_Reference
R298 R304 R308 = CMP-0026542-2: RES, 750, 1%, 0.063 W, AEC-Q200 Grade 0, 0402; Manufacturer: Vishay-Dale; Power_W: 63mW; TempCo: 100 ppm/C; Value_Code: 750R; Value: 750; EIA_Code: E96; SizeX_mm: 1; SizeY_mm: 0.5; SizeZ_mm: 0.6; Value2: 0.063W; AEC Qualified: Y; VDC_V: 50V; AEC Grade: 0; AEC Category: Q200
R299 R305 R310 = CMP-0025958-3: as R102 on sheet PROC196A_PMIC_Reference
R300 R306 R311 = CMP-0026557-2: RES, 7.87 k, 1%, 0.063 W, AEC-Q200 Grade 0, 0402; Manufacturer: Vishay-Dale; Power_W: 63mW; TempCo: 100 ppm/C; Value_Code: 7k87; Value: 7.87k; EIA_Code: E96; SizeX_mm: 1; SizeY_mm: 0.5; SizeZ_mm: 0.6; Value2: 0.063W; AEC Qualified: Y; VDC_V: 50V; AEC Grade: 0; AEC Category: Q200
R301 R303 R309 R312 = CMP-0025958-3: RES, 10.0 k, 1%, 0.063 W, AEC-Q200 Grade 0, 0402; Manufacturer: Vishay-Dale; Power_W: 63mW; TempCo: 100 ppm/C; Value_Code: 10k0; Value: 10.0k; EIA_Code: E96; Res_ohm: 10k; SizeX_mm: 1; SizeY_mm: 0.5; SizeZ_mm: 0.6; Value2: 0.063W; CompType: Resistor; AEC Qualified: Y; VDC_V: 50V; AEC Category: Q200; AEC Grade: 0; INSTALLATION: DNP
R302 R307 R313 = CMP-0026574-2: RES, 82.5 k, 1%, 0.063 W, AEC-Q200 Grade 0, 0402; Manufacturer: Vishay-Dale; Power_W: 63mW; TempCo: 100 ppm/C; Value_Code: 82k5; Value: 82.5k; EIA_Code: E96; SizeX_mm: 1; SizeY_mm: 0.5; SizeZ_mm: 0.6; Value2: 0.063W; AEC Qualified: Y; VDC_V: 50V; AEC Grade: 0; AEC Category: Q200

## Sheet PROC196A_PWR_RST_LED.SchDoc
size 431 x 279 mm; Date: Not shown in title block; ApprovedBy: Not shown in title block; CheckedBy: Not shown in title block; Author: Not shown in title block; CompanyName: Not shown in title block; Engineer: Not shown in title block; Organization: Not shown in title block; Address1: Not shown in title block; Address2: Not shown in title block; Address3: Not shown in title block; Address4: Not shown in title block; DocumentNumber: 9; Revision: Use project parameter SCH_Rev; SheetNumber: 9; SheetTotal: 25; PageSetup: Record=PageOptions¦CenterHorizontal=True¦CenterVertical=True¦PrintScale=1.00¦XCorrection=1.00¦YCorrection=1.00¦PrintKind=0¦BorderSize=5000000¦LeftOffset=0¦BottomOffset=0¦Orientation=2¦PaperLength=1000¦PaperWidth=1000¦Scale=100¦PaperSource=15¦PrintQuality=600¦MediaType=1¦DitherType=10¦PaperKind=Letter¦PrintScaleMode=1
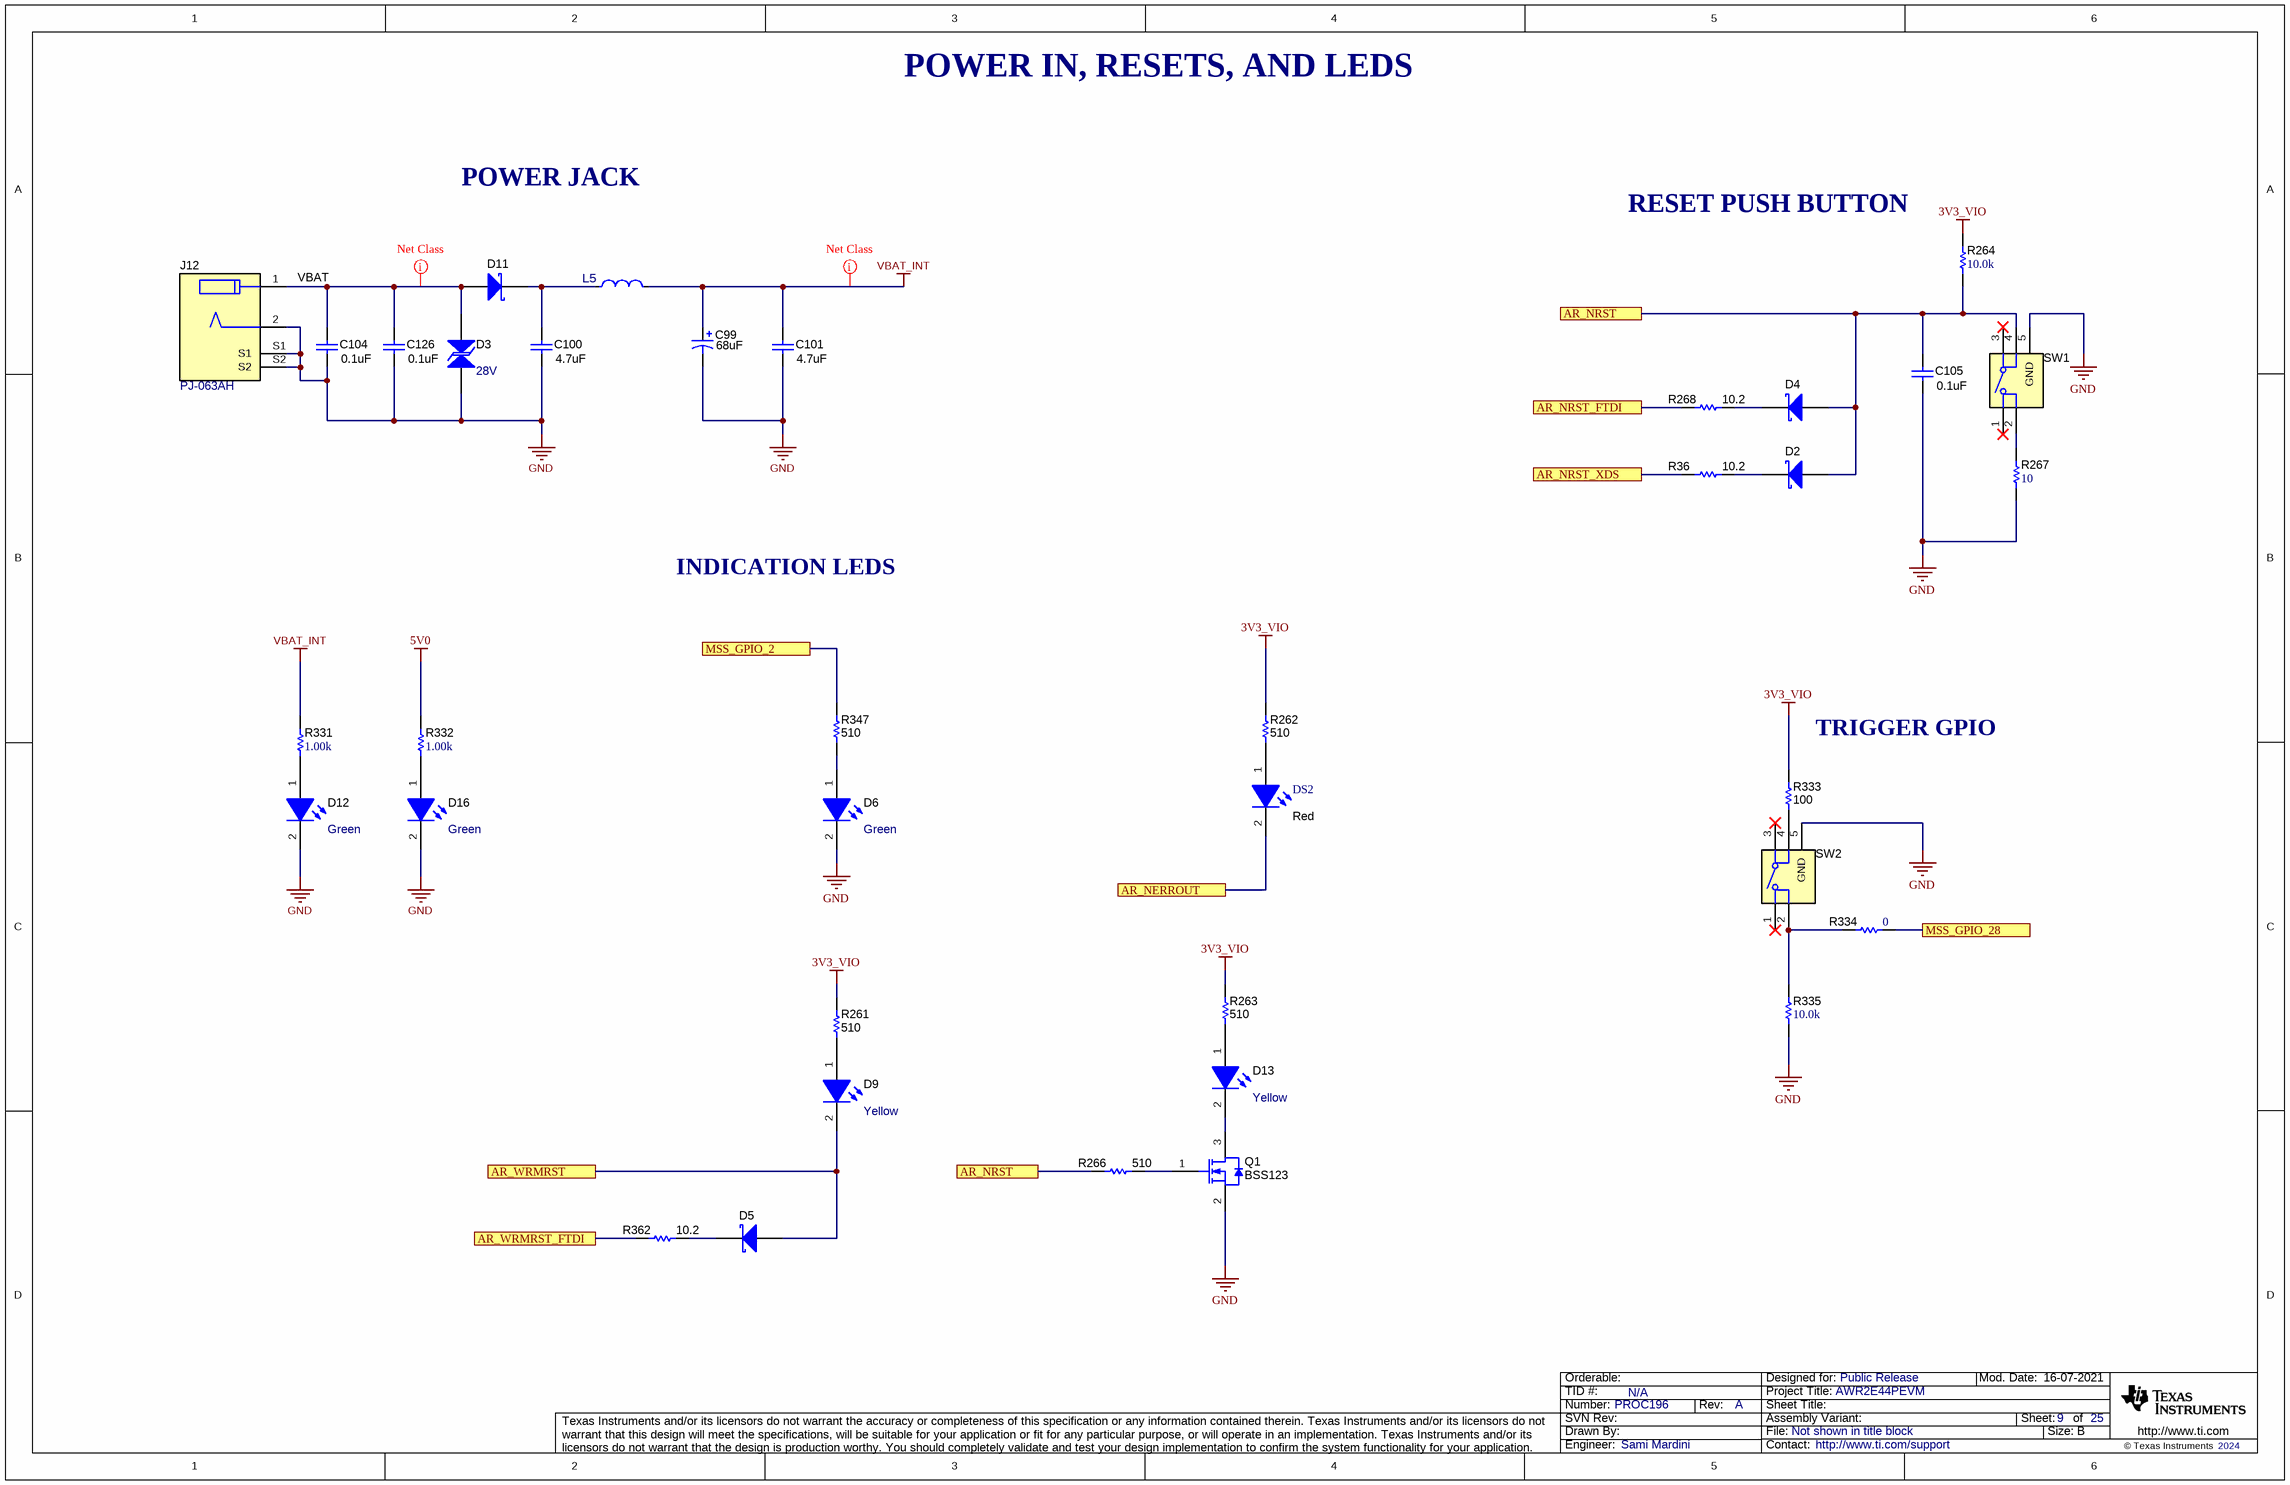
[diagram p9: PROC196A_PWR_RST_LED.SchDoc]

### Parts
C99  ValueDisplayed: 68uF  [SM_RADIAL_6.3BMM]  (hidden comment: EEHZC1V680XP)
C100  ValueDisplayed: 4.7uF  [1206_180L]  (hidden comment: C3216X7R1H475K160AC)
C101  ValueDisplayed: 4.7uF  [1206_180L]  (hidden comment: C3216X7R1H475K160AC)
C104  ValueDisplayed: 0.1uF  [0603L]  (hidden comment: CGA3E3X8R1H104K080AB)
C105  ValueDisplayed: 0.1uF  [0402L]  (hidden comment: GCM155R71C104KA55D)
C126  ValueDisplayed: 0.1uF  [0603L]  (hidden comment: CGA3E3X8R1H104K080AB)
D2  SMS3923-040LF  [SOD-882]  (value not drawn)
D3  value 28V  [SOD-123]  (hidden comment: ATV02W280B-HF)
D4  SMS3923-040LF  [SOD-882]  (value not drawn)
D5  SMS3923-040LF  [SOD-882]  (value not drawn)
D6  value Green  [SML_Green_0805]  (hidden comment: SML-LXT0805GW-TR)
D9  value Yellow  [SML-E1_Yellow]  (hidden comment: SML-E12Y8WT86)
D11  PMEG3050EP,115  [SOD-128]  (value not drawn)
D12  value Green  [SML_Green_0805]  (hidden comment: SML-LXT0805GW-TR)
D13  value Yellow  [SML-E1_Yellow]  (hidden comment: SML-E12Y8WT86)
D16  value Green  [SML_Green_0805]  (hidden comment: SML-LXT0805GW-TR)
DS2  value Red  [LS L29K_Red]  (hidden comment: LS L29K-G1J2-1-Z)
J12  PJ-063AH  [CUI_PJ-063AH]
L5  XAL4030-472MEC  [FP-XAL4030-472MEC_SMD2-MFG]  (value not drawn)
Q1  BSS123  [SOT-23]
R36  ValueDisplayed: 10.2  [0402L]  (hidden comment: CRCW040210R2FKED)
R261  ValueDisplayed: 510  [0402L]  (hidden comment: ERJ-2GEJ511X)
R262  ValueDisplayed: 510  [0402L]  (hidden comment: ERJ-2GEJ511X)
R263  ValueDisplayed: 510  [0402L]  (hidden comment: ERJ-2GEJ511X)
R264  ValueDisplayed: 10.0k  [0402L]  (hidden comment: CRCW040210K0FKED)
R266  ValueDisplayed: 510  [0402L]  (hidden comment: ERJ-2GEJ511X)
R267  ValueDisplayed: 10  [0402L]  (hidden comment: CRCW040210R0JNED)
R268  ValueDisplayed: 10.2  [0402L]  (hidden comment: CRCW040210R2FKED)
R331  ValueDisplayed: 1.00k  [0402L]  (hidden comment: CRCW04021K00FKED)
R332  ValueDisplayed: 1.00k  [0402L]  (hidden comment: CRCW04021K00FKED)
R333  ValueDisplayed: 100  [0402L]  (hidden comment: ERJ-2GEJ101X)
R334  ValueDisplayed: 0  [0201L]  (hidden comment: CRCW02010000Z0ED)
R335  ValueDisplayed: 10.0k  [0402L]  (hidden comment: CRCW040210K0FKED)
R347  ValueDisplayed: 510  [0402L]  (hidden comment: ERJ-2GEJ511X)
R362  ValueDisplayed: 10.2  [0402L]  (hidden comment: CRCW040210R2FKED)
SW1  KMR243GLFG  [SW_KMR243GLFG]  (value not drawn)
SW2  KMR243GLFG  [SW_KMR243GLFG]  (value not drawn)

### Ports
AR_NERROUT, AR_NRST, AR_NRST_FTDI, AR_NRST_XDS, AR_WRMRST, AR_WRMRST_FTDI, MSS_GPIO_2, MSS_GPIO_28

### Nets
3V3_VIO: R261.2 R262.2 R263.2 R264.2 R333.2
5V0: R332.2
GND: C99.2(-) C100.2 C101.2 C104.2 C105.1 C126.2 D3.1 D6.2(K) D12.2(K) D16.2(K) J12.2 J12.S1 J12.S2 Q1.2(S) R267.1 R335.1 SW1.5(GND) SW2.5(GND)
VBAT_INT: C99.1(+) C101.1 L5.2 R331.2
AR_NERROUT: DS2.2(K) ; port AR_NERROUT
AR_NRST: C105.2 D2.2(A) D4.2(A) R264.1 R266.1 SW1.4 ; port AR_NRST
AR_NRST_FTDI: R268.1 ; port AR_NRST_FTDI
AR_NRST_XDS: R36.1 ; port AR_NRST_XDS
AR_WRMRST: D5.2(A) D9.2(K) ; port AR_WRMRST
AR_WRMRST_FTDI: R362.1 ; port AR_WRMRST_FTDI
MSS_GPIO_2: R347.2 ; port MSS_GPIO_2
MSS_GPIO_28: R334.2 ; port MSS_GPIO_28
NetC100_1: C100.1 D11.1(K) L5.1
NetC104_1: C104.1 C126.1 D3.2 D11.2(A) J12.1
NetD2_1: D2.1(K) R36.2
NetD4_1: D4.1(K) R268.2
NetD5_1: D5.1(K) R362.2
NetD6_1: D6.1(A) R347.1
NetD9_1: D9.1(A) R261.1
NetD12_1: D12.1(A) R331.1
NetD13_1: D13.1(A) R263.1
NetD13_2: D13.2(K) Q1.3(D)
NetD16_1: D16.1(A) R332.1
NetDS2_1: DS2.1(A) R262.1
NetQ1_1: Q1.1(G) R266.2
NetR267_2: R267.2 SW1.2
NetR333_1: R333.1 SW2.4
NetR334_1: R334.1 R335.2 SW2.2

Not connected (* = marked no-connect by the designer): SW1 1* 3*; SW2 1* 3*

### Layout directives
net class PWR: NetC104_1, VBAT_INT

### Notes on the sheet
- POWER IN, RESETS, AND LEDS
- POWER JACK
- RESET PUSH BUTTON
- VBAT
- INDICATION LEDS
- (near R333) TRIGGER GPIO

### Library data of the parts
C99 = CMP-0012608-3: CAP, Polymer Hybrid, 68 uF, 35 V, +/- 20%, 35 ohm, 6.3x7.7 SMD; Manufacturer: Panasonic; TaMin_C: -55°C; ESR_ohm: 35; Polarized: Y; SizeAreaWB_mm2: 79.98; Value1: 35 ohm; Value: 68uF; TaMax_C: 125°C; SizeZ_mm: 7.7; SizeX_mm: 7.3; SizeY_mm: 6.6; Value2: 35V; SizeArea_mm2: 48.18; CompType: Capacitor; Cap_F: 68µF; IRMS_A: 1.4A; AEC Category: Q200
C100 C101 = CMP-0008702-2: CAP, CERM, 4.7 uF, 50 V, +/- 10%, X7R, 1206; Manufacturer: TDK; TaMin_C: -55°C; ESR_ohm: 3.158m; Polarized: N; SizeAreaWB_mm2: 10.92; Value1: 0.003158 ohm; U/M: EA; Value: 4.7uF; TaMax_C: 125°C; SizeZ_mm: 1.8; SizeX_mm: 3.2; SizeY_mm: 1.6; Cap_Case: 1206_180; Value2: 50V; SizeArea_mm2: 5.12; Cap_F: 4.7µF; IRMS_A: 4.08379A; AEC Category: Q200
C104 C126 = CMP-0007104-4: CAP, CERM, 0.1 uF, 50 V, +/- 10%, X8R, AEC-Q200 Grade 0, 0603; Manufacturer: TDK; TaMin_C: -55°C; Polarized: N; SizeAreaWB_mm2: 4.68; Value1: Unknown; U/M: EA; Value: 0.1uF; TaMax_C: 150°C; SizeZ_mm: 1; SizeX_mm: 1.6; SizeY_mm: 0.8; Cap_Case: 0603; Value2: 50V; SizeArea_mm2: 1.28; AEC Qualified: Y; Cap_F: 100nF; AEC Grade: 0; AEC Category: Q200
C105 = CMP-0006351-2: as C200 on sheet PROC196A_PMIC_Reference
D2 D4 D5 = CMP-0078187-3: Diode, Schottky,  V, 0.01 A, SOD-882; Manufacturer: Skyworks Solutions; SizeArea_mm2: 0.6; SizeAreaWB_mm2: 3.2; Io_A: 10mA; SizeX_mm: 1; Value1: 0.01A; SizeZ_mm: 0.5; Value2: 0.34V; AEC Category: Q101; Vf_V: 340mV; TJmax_C: 150°C; AEC Qualified: N
D3 = CMP-0005735-3: Diode, TVS, Bi, 28 V, 45.4 Vc, AEC-Q101, SOD-123; Manufacturer: Comchip Technology; SizeAreaWB_mm2: 13.095; Value1: 200W; SizeZ_mm: 1.35; SizeX_mm: 3.85; SizeY_mm: 1.7; SizeArea_mm2: 6.545; AEC Qualified: Y; AEC Category: Q101; Ipp: 4.41A; Vbr_Max: 34.4V; Vbr_Min: 31.1V; Vc: 45.4V
D6 D12 D16 = CMP-0003042-3: LED, Green, SMD; Manufacturer: Lumex; SizeZ_mm: 0.8; Power_TotalModule: 50mW; Value2: 2V; SizeY_mm: 1.25; Tjmax_C: 80°C; SizeX_mm: 2; SizeAreaWB_mm2: 6.75; Ir_A: 100µA; Angle: 140; Vr_V: 5V; Io_A: 20mA; Value1: 0.05W; SizeArea_mm2: 2.5
D9 D13 = CMP-0002977-3: LED, Yellow, SMD; Manufacturer: Rohm; Vf_V: 2.2V; Vr_V: 5V; Ir_A: 10µA; Tjmax_C: 85°C; Io_A: 20mA; LuminousIntensity_IV: 63; Power_TotalModule: 54mW; Value1: 0.054W
D11 = CMP-0077017-3: Diode, Schottky, 30 V, 5 A, SOD-128; Manufacturer: Nexperia; Vf_V: 360mV; Vr_V: 30V; Green_Lifecycle: Not Set; SizeZ_mm: 1.1; SizeY_mm: 2.5; Value2: 0.36V; Value1: 5A; SizeAreaWB_mm2: 19.6; AEC Category: Q101; SizeArea_mm2: 11.5; Green_REACh: Incomplete; TJmax_C: 150°C; SizeX_mm: 4.6; Value: 30V
DS2 = CMP-0002902-2: LED, Red, SMD; Manufacturer: OSRAM; Io_A: 20mA; Vr_V: 12V; Tjmax_C: 110°C; Value1: W; Angle: 160; Vf_V: 1.8V
J12 = CMP-0079472-1: DC POWER JACK, R/A, TH; Manufacturer: CUI Inc.; Gender: Male; Cert_UL: Y; Current_A: 8A; Voltage_V: 24V
L5 = CMP-0089502-2: Power Inductor (SMD), 4.7 µH, 5.1 A, Shielded, 4.5 A, XAL40xx Series, 4mm x 4mm x 3.1mm; Manufacturer: Coilcraft; Material: Composite; TaMin_C: -40°C; Test Frequency: 1MHz; Shrouded: true; Irms: 5.1A; AEC Grade: Grade 1; Tolerance_%: 20%; Isat: 4.5A; AEC Qualified: Yes; Standoff Height: 0.08mm; DCR_ohm: 0.0441; Self Resonant Frequency: 36MHz; Ind_H: 4.7µH; TaMax_C: +125°C; Value: 4.7µH
Q1 = CMP-0000947-2: MOSFET, N-CH, 100 V, 0.17 A, SOT-23; Alternate Manufacturer: None; Manufacturer: Fairchild Semiconductor; SizeZ_mm: 1.1; ChType: N; Value2: 1.8 nC; Value1: 1; VdsMax_V: 100V; SizeX_mm: 2.5; SizeY_mm: 3; Vgs_V: 20V; Value: 100V; Rdson45_ohm: 10; SizeArea_mm2: 7.5; AEC Category: Q101; IdsMax_A: 1.7dA; SizeAreaWB_mm2: 14; U/M: EA; QgTyp_nC: 1.8
R36 R268 R362 = CMP-0025964-3: RES, 10.2, 1%, 0.063 W, AEC-Q200 Grade 0, 0402; Manufacturer: Vishay-Dale; Power_W: 63mW; TempCo: 100 ppm/C; Value_Code: 10R2; Value: 10.2; EIA_Code: E96; SizeX_mm: 1; SizeY_mm: 0.5; SizeZ_mm: 0.6; Value2: 0.063W; AEC Qualified: Y; VDC_V: 50V; AEC Category: Q200; AEC Grade: 0
R261-R263 R266 R347 = CMP-0078212-1: as R292 on sheet PROC196A_PMIC_Reference
R264 R335 = CMP-0025958-3: as R102 on sheet PROC196A_PMIC_Reference
R267 = CMP-0026827-3: RES, 10, 5%, 0.063 W, AEC-Q200 Grade 0, 0402; Manufacturer: Vishay-Dale; Power_W: 63mW; TempCo: 200 ppm/C; Value_Code: 10R0; Value: 10; EIA_Code: E24; SizeX_mm: 1; SizeY_mm: 0.5; SizeZ_mm: 0.6; Value2: 0.063W; AEC Qualified: Y; VDC_V: 50V; AEC Category: Q200; AEC Grade: 0
R331 R332 = CMP-0026071-3: as R99 on sheet PROC196A_PMIC_Reference
R333 = CMP-0026993-2: RES, 100, 5%, 0.1 W, AEC-Q200 Grade 0, 0402; Manufacturer: Panasonic; Power_W: 100mW; TempCo: 200 ppm/C; Value_Code: 100R; U/M: EA; Value: 100; EIA_Code: E24; SizeX_mm: 1; SizeY_mm: 0.5; SizeZ_mm: 0.6; Value2: 0.1W; AEC Qualified: Y; AEC Grade: 0; AEC Category: Q200
R334 = CMP-0027008-4: RES, 0, 5%, 0.05 W, 0201; Manufacturer: Vishay-Dale; Power_W: 50mW; TempCo: ppm/C; Value_Code: 0000; Value: 0; EIA_Code: E24; SizeX_mm: 0.6; SizeY_mm: 0.3; SizeZ_mm: 0.26; Value2: 0.05W; SizeArea_mm2: 0.18; AEC Qualified: N; AEC Category: Q200
SW1 SW2 = CMP-0002325-1: Switch, SPST-NO, Off-Mom, 0.01 A, 32 VDC, SMD; Manufacturer: C&K Components; CurrentRating_mA: 10A; PositionCount: 1; SizeX_mm: 4.6; SizeY_mm: 2.8; SizeZ_mm: 1.9; SizeArea_mm2: 12.88; VDC_V: 32V; SizeAreaWB_mm2: 21.28

## Sheet PROC196A_VPP_LDO.SchDoc
size 431 x 279 mm; Date: Not shown in title block; ApprovedBy: Not shown in title block; CheckedBy: Not shown in title block; Author: Not shown in title block; CompanyName: Not shown in title block; Engineer: Not shown in title block; Organization: Not shown in title block; Address1: Not shown in title block; Address2: Not shown in title block; Address3: Not shown in title block; Address4: Not shown in title block; DocumentNumber: 10; Revision: Use project parameter SCH_Rev; SheetNumber: 10; SheetTotal: 25; PageSetup: Record=PageOptions¦CenterHorizontal=True¦CenterVertical=True¦PrintScale=1.00¦XCorrection=1.00¦YCorrection=1.00¦PrintKind=0¦BorderSize=5000000¦LeftOffset=0¦BottomOffset=0¦Orientation=2¦PaperLength=1000¦PaperWidth=1000¦Scale=100¦PaperSource=15¦PrintQuality=600¦MediaType=1¦DitherType=10¦PaperKind=Letter¦PrintScaleMode=1
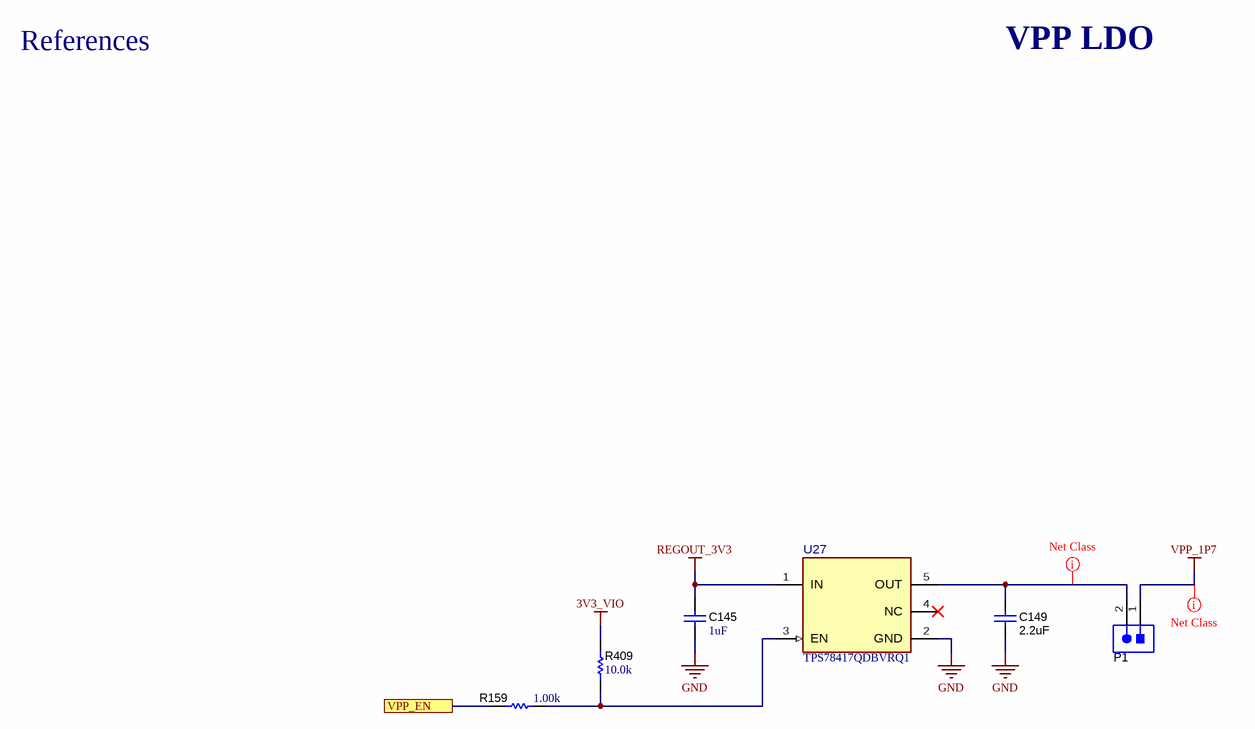
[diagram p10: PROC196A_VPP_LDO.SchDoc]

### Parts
C145  ValueDisplayed: 1uF  [0603L]  (hidden comment: GCM188R71C105KA64D)
C149  ValueDisplayed: 2.2uF  [0603L]  (hidden comment: GCM188R70J225KE22D)
P1  TSW-102-07-G-S  [TSW-102-07-G-S]  (value not drawn)
R159  ValueDisplayed: 1.00k  [0402L]  (hidden comment: CRCW04021K00FKED)
R409  ValueDisplayed: 10.0k  [0402L]  (hidden comment: CRCW040210K0FKED)
U27  TPS78417QDBVRQ1  [DBV0005A-MFG]

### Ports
VPP_EN

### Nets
3V3_VIO: R409.2
GND: C145.2 C149.1 U27.2(GND)
REGOUT_3V3: C145.1 U27.1(IN)
VPP_1P7: P1.1
VPP_EN: R159.1 ; port VPP_EN
NetC149_2: C149.2 P1.2 U27.5(OUT)
NetR159_2: R159.2 R409.1 U27.3(EN)

Not connected (* = marked no-connect by the designer): U27 4(NC)*

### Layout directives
net class PWR: NetC149_2, VPP_1P7

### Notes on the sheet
- References
- VPP LDO

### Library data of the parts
C145 = CMP-0007136-5: CAP, CERM, 1 uF, 16 V, +/- 10%, X7R, AEC-Q200 Grade 1, 0603; Manufacturer: MuRata; TaMin_C: -55°C; Polarized: N; SizeAreaWB_mm2: 4.68; Value1: Unknown; U/M: EA; Value: 1uF; TaMax_C: 125°C; SizeZ_mm: 1; SizeX_mm: 1.6; SizeY_mm: 0.8; Cap_Case: 0603; Value2: 16V; SizeArea_mm2: 1.28; CompType: Capacitor; AEC Qualified: Y; Cap_F: 1µF; AEC Category: Q200
C149 = CMP-0007134-5: as C3 on sheet PROC196A_PMIC_Reference
P1 = CMP-0075405-3: Header, 100mil, 2x1, Gold, TH; Manufacturer: Samtec; Pitch_mm: 2.54; Cert_VDE: N; Gender: Male; Cert_CSA: Y; Voltage_V: 550V; Green_REACh: Passed; Current_A: 6.3A; Green_Lifecycle: Active; Row_Count: 1
R159 = CMP-0026071-3: as R99 on sheet PROC196A_PMIC_Reference
R409 = CMP-0025958-3: as R102 on sheet PROC196A_PMIC_Reference
U27 = CMP-0092338-1: Linear Voltage Regulator IC Positive Fixed Output 300mA SOT-23-5; Manufacturer: Texas Instruments; TaMin_C: -40°C; Output Voltage: 1.7V; Standoff Height: 0mm; SizeZ_mm: 1.45mm; TaMax_C: +125°C; Accuracy Percentage: 0.5%; AEC Grade: Grade 1; Number Of Outputs: 1; AEC Qualified: Yes; Max Supply Voltage: 6V; Dropout Voltage: 900mV; Nominal Supply Current: 0.033mA; Min Supply Voltage: 1.65V; TJmax_C: +150°C

## Sheet PROC196A_Ethernet_PWR.SchDoc
size 431 x 279 mm; Date: Not shown in title block; ApprovedBy: Not shown in title block; CheckedBy: Not shown in title block; Author: Not shown in title block; CompanyName: Not shown in title block; Engineer: Not shown in title block; Organization: Not shown in title block; Address1: Not shown in title block; Address2: Not shown in title block; Address3: Not shown in title block; Address4: Not shown in title block; DocumentNumber: 11; Revision: Use project parameter SCH_Rev; SheetNumber: 11; SheetTotal: 25; PageSetup: Record=PageOptions¦CenterHorizontal=True¦CenterVertical=True¦PrintScale=1.00¦XCorrection=1.00¦YCorrection=1.00¦PrintKind=0¦BorderSize=5000000¦LeftOffset=0¦BottomOffset=0¦Orientation=2¦PaperLength=1000¦PaperWidth=1000¦Scale=100¦PaperSource=15¦PrintQuality=600¦MediaType=1¦DitherType=10¦PaperKind=Letter¦PrintScaleMode=1
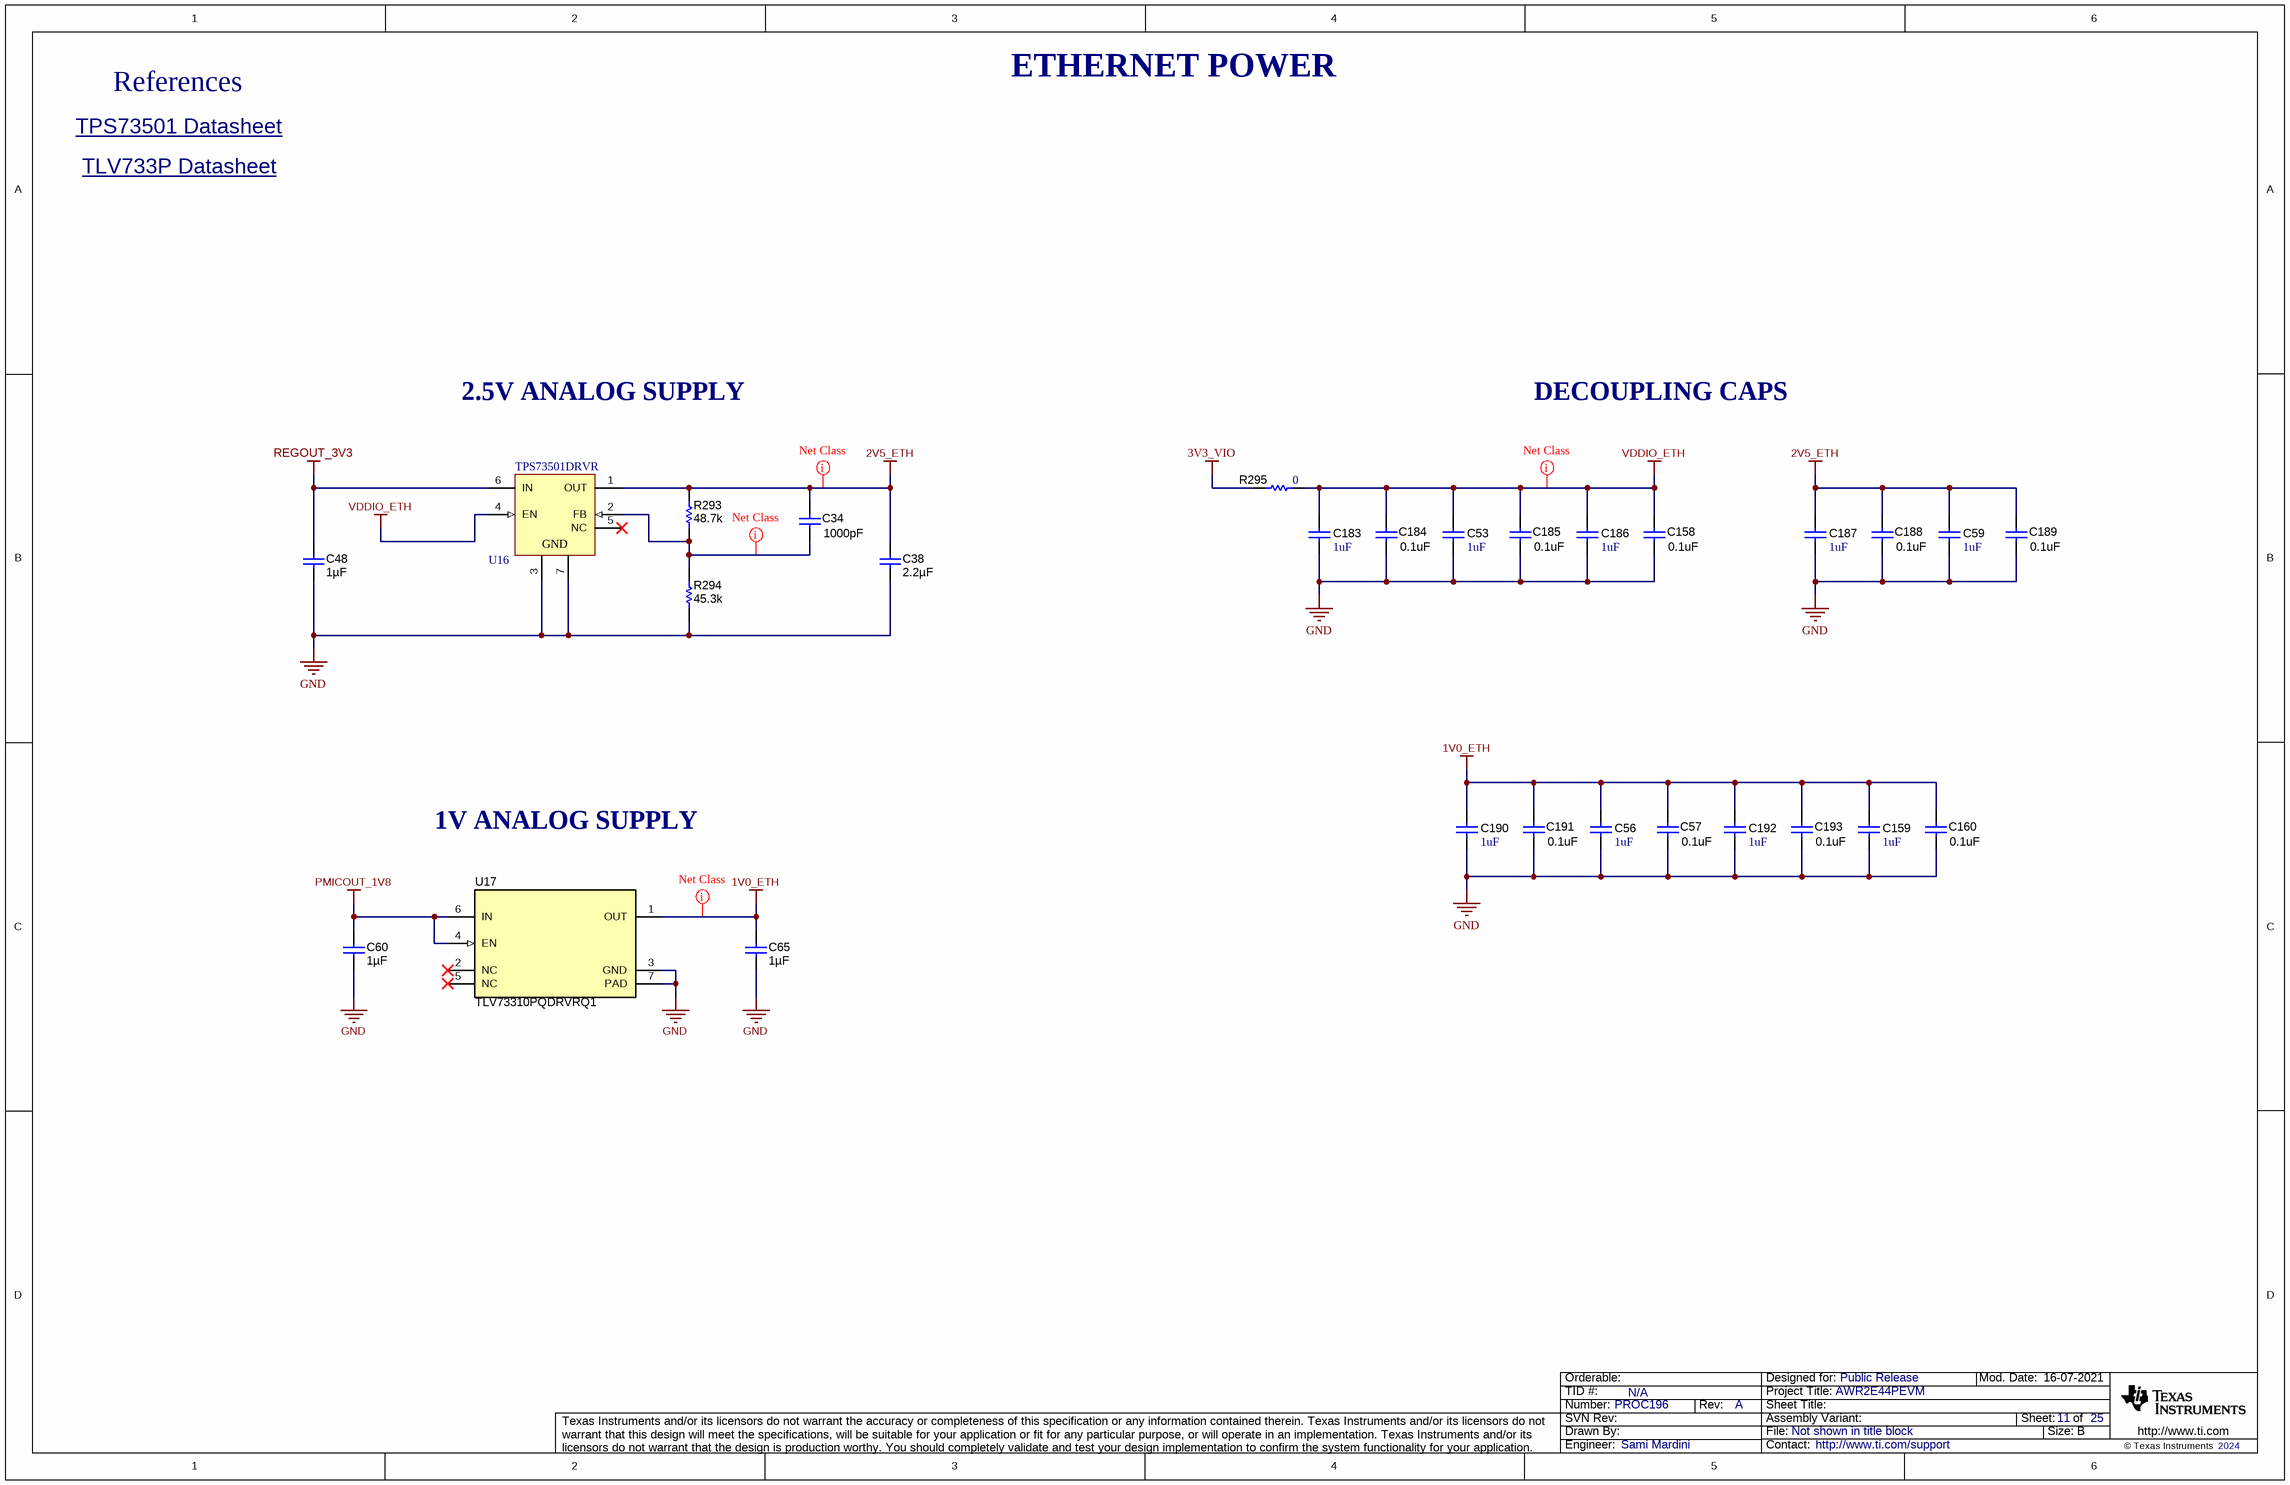
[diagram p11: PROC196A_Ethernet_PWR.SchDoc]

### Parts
C34  ValueDisplayed: 1000pF  [0402L]  (hidden comment: GCM155R71H102KA37D)
C38  Cap_F: 2.2µF  [0805L]  (hidden comment: CGA4J3X7R1H225K125AB)
C48  Cap_F: 1µF  [0603L]  (hidden comment: GCM188R71C105KA64D)
C53  ValueDisplayed: 1uF  [0603L]  (hidden comment: GCM188R71C105KA64D)
C56  ValueDisplayed: 1uF  [0603L]  (hidden comment: GCM188R71C105KA64D)
C57  ValueDisplayed: 0.1uF  [0402L]  (hidden comment: GCM155R71A104KA55D)
C59  ValueDisplayed: 1uF  [0603L]  (hidden comment: GCM188R71C105KA64D)
C60  Cap_F: 1µF  [0603L]  (hidden comment: GCM188R71C105KA64D)
C65  Cap_F: 1µF  [0603L]  (hidden comment: GCM188R71C105KA64D)
C158  ValueDisplayed: 0.1uF  [0402L]  (hidden comment: GCM155R71A104KA55D)
C159  ValueDisplayed: 1uF  [0603L]  (hidden comment: GCM188R71C105KA64D)
C160  ValueDisplayed: 0.1uF  [0402L]  (hidden comment: GCM155R71A104KA55D)
C183  ValueDisplayed: 1uF  [0603L]  (hidden comment: GCM188R71C105KA64D)
C184  ValueDisplayed: 0.1uF  [0402L]  (hidden comment: GCM155R71A104KA55D)
C185  ValueDisplayed: 0.1uF  [0402L]  (hidden comment: GCM155R71A104KA55D)
C186  ValueDisplayed: 1uF  [0603L]  (hidden comment: GCM188R71C105KA64D)
C187  ValueDisplayed: 1uF  [0603L]  (hidden comment: GCM188R71C105KA64D)
C188  ValueDisplayed: 0.1uF  [0402L]  (hidden comment: GCM155R71A104KA55D)
C189  ValueDisplayed: 0.1uF  [0402L]  (hidden comment: GCM155R71A104KA55D)
C190  ValueDisplayed: 1uF  [0603L]  (hidden comment: GCM188R71C105KA64D)
C191  ValueDisplayed: 0.1uF  [0402L]  (hidden comment: GCM155R71A104KA55D)
C192  ValueDisplayed: 1uF  [0603L]  (hidden comment: GCM188R71C105KA64D)
C193  ValueDisplayed: 0.1uF  [0402L]  (hidden comment: GCM155R71A104KA55D)
R293  ValueDisplayed: 48.7k  [0603L]  (hidden comment: CRCW060348K7FKEA)
R294  ValueDisplayed: 45.3k  [0603L]  (hidden comment: CRCW060345K3FKEA)
R295  ValueDisplayed: 0  [0402L]  (hidden comment: ERJ-2GE0R00X)
U16  TPS73501DRVR  [DRV0006A]
U17  TLV73310PQDRVRQ1  [DRV0006A]

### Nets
1V0_ETH: C56.1 C57.1 C65.1 C159.1 C160.1 C190.1 C191.1 C192.1 C193.1 U17.1(OUT)
2V5_ETH: C34.1 C38.1 C59.1 C187.1 C188.1 C189.1 R293.2 U16.1(OUT)
3V3_VIO: R295.2
GND: C38.2 C48.2 C53.2 C56.2 C57.2 C59.2 C60.2 C65.2 C158.2 C159.2 C160.2 C183.2 C184.2 C185.2 C186.2 C187.2 C188.2 C189.2 C190.2 C191.2 C192.2 C193.2 R294.1 U16.3(GND) U16.7(GND) U17.3(GND) U17.7(PAD)
PMICOUT_1V8: C60.1 U17.4(EN) U17.6(IN)
REGOUT_3V3: C48.1 U16.6(IN)
VDDIO_ETH: C53.1 C158.1 C183.1 C184.1 C185.1 C186.1 R295.1 U16.4(EN)
NetC34_2: C34.2 R293.1 R294.2 U16.2(FB)

Not connected (* = marked no-connect by the designer): U16 5(NC)*; U17 2(NC)* 5(NC)*

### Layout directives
net class PWR: 1V0_ETH, 2V5_ETH, NetC34_2, VDDIO_ETH

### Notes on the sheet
- References
- ETHERNET POWER
- TPS73501 Datasheet <http://www.ti.com/lit/ds/symlink/tps735.pdf>
- TLV733P Datasheet <http://www.ti.com/lit/ds/symlink/tlv733p.pdf>
- 2.5V ANALOG SUPPLY
- DECOUPLING CAPS
- 1V ANALOG SUPPLY

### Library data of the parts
C34 = CMP-0006354-2: CAP, CERM, 1000 pF, 50 V, +/- 10%, X7R, AEC-Q200 Grade 1, 0402; Manufacturer: MuRata; TaMin_C: -55°C; Polarized: N; SizeAreaWB_mm2: 3; Value1: Unknown; U/M: EA; Value: 1000pF; TaMax_C: 125°C; SizeZ_mm: 0.6; SizeX_mm: 1; SizeY_mm: 0.5; Cap_Case: 0402; Value2: 50V; AEC Qualified: Y; Cap_F: 1nF; AEC Category: Q200
C38 = CMP-0007977-2: CAP, CERM, 2.2 uF, 50 V, +/- 10%, X7R, AEC-Q200 Grade 1, 0805; Manufacturer: TDK; TaMin_C: -55°C; ESR_ohm: 3.288m; Polarized: N; SizeAreaWB_mm2: 6.75; Value1: 0.003288 ohm; U/M: EA; Value: 2.2uF; TaMax_C: 125°C; SizeZ_mm: 1.45; SizeX_mm: 2; SizeY_mm: 1.25; Cap_Case: 0805; Value2: 50V; SizeArea_mm2: 2.5; AEC Qualified: Y; IRMS_A: 3.60029A; AEC Grade: 1; AEC Category: Q200
C48 C60 C65 = CMP-0007136-5: as C10 on sheet PROC196A_3V3_Supply_Reference
C53 C56 C59 C159 C183 C186 C187 C190 C192 = CMP-0007136-5: as C145 on sheet PROC196A_VPP_LDO
C57 C158 C160 C184 C185 C188 C189 C191 C193 = CMP-0006350-2: CAP, CERM, 0.1 uF, 10 V, +/- 10%, X7R, AEC-Q200 Grade 1, 0402; Manufacturer: MuRata; TaMin_C: -55°C; Polarized: N; SizeAreaWB_mm2: 3; Value1: Unknown; U/M: EA; Value: 0.1uF; TaMax_C: 125°C; SizeZ_mm: 0.6; SizeX_mm: 1; SizeY_mm: 0.5; Cap_Case: 0402; Value2: 10V; AEC Qualified: Y; Cap_F: 100nF; AEC Category: Q200
R293 = CMP-0022443-4: RES, 48.7 k, 1%, 0.1 W, AEC-Q200 Grade 0, 0603; Manufacturer: Vishay-Dale; Power_W: 100mW; TempCo: 100 ppm/C; Value_Code: 48k7; Value: 48.7k; EIA_Code: E96; SizeX_mm: 1.6; SizeY_mm: 0.8; SizeZ_mm: 1; Value2: 0.1W; SizeArea_mm2: 1.28; AEC Qualified: Y; VDC_V: 75V; AEC Category: Q200; AEC Grade: 0
R294 = CMP-0022430-4: RES, 45.3 k, 1%, 0.1 W, AEC-Q200 Grade 0, 0603; Manufacturer: Vishay-Dale; Power_W: 100mW; TempCo: 100 ppm/C; Value_Code: 45k3; Value: 45.3k; EIA_Code: E96; SizeX_mm: 1.6; SizeY_mm: 0.8; SizeZ_mm: 1; Value2: 0.1W; SizeArea_mm2: 1.28; AEC Qualified: Y; VDC_V: 75V; AEC Category: Q200; AEC Grade: 0
R295 = CMP-0026992-3: as R5 on sheet PROC196A_PMIC_Reference
U16 = CMP-0036314-5: Single Output High PSRR LDO, 500 mA, Adjustable 1.25 to 6 V Output, 2.7 to 6.5 V Input, with Low IQ, 6-pin SON (DRV), -40 to 125 degC, Green (RoHS & no Sb/Br); Manufacturer: Texas Instruments; SubFamily: Single Channel LDO; Vin(Max)(V): 6.5; Vin(Min)(V): 2.7; Iout(Max)(A): 0.5; Iq(Typ)(mA): 0.04; Vdo(Typ)(mV): 280; Vout Adj(Max)(V): 6; Vout Adj(Min)(V): 1.25; Accuracy(%): 2; CompType: IC; SizeAreaWB_mm2: 9; SizeArea_mm2: 4; SizeZ_mm: 0.8
U17 = CMP-0078869-1: Capacitor-Free, 300-mA, Low-Dropout Regulator for Automotive, DRV0006A (WSON-6); Alternate Manufacturer: Texas Instruments; SizeAreaWB_mm2: 9; SizeZ_mm: 0.8; SizeX_mm: 2; SizeArea_mm2: 4; CompType: IC; AEC Qualified: Y; AEC Category: Q200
